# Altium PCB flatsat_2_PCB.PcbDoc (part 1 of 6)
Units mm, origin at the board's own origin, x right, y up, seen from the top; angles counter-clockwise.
Board outline 400 x 250 mm, 4 copper layers (Top Layer, FlatSat GND, FlatSat VCC, Bottom Layer), stack 2.102 mm thick; 196 components, 289 nets, 1724 pads, 1139 vias.
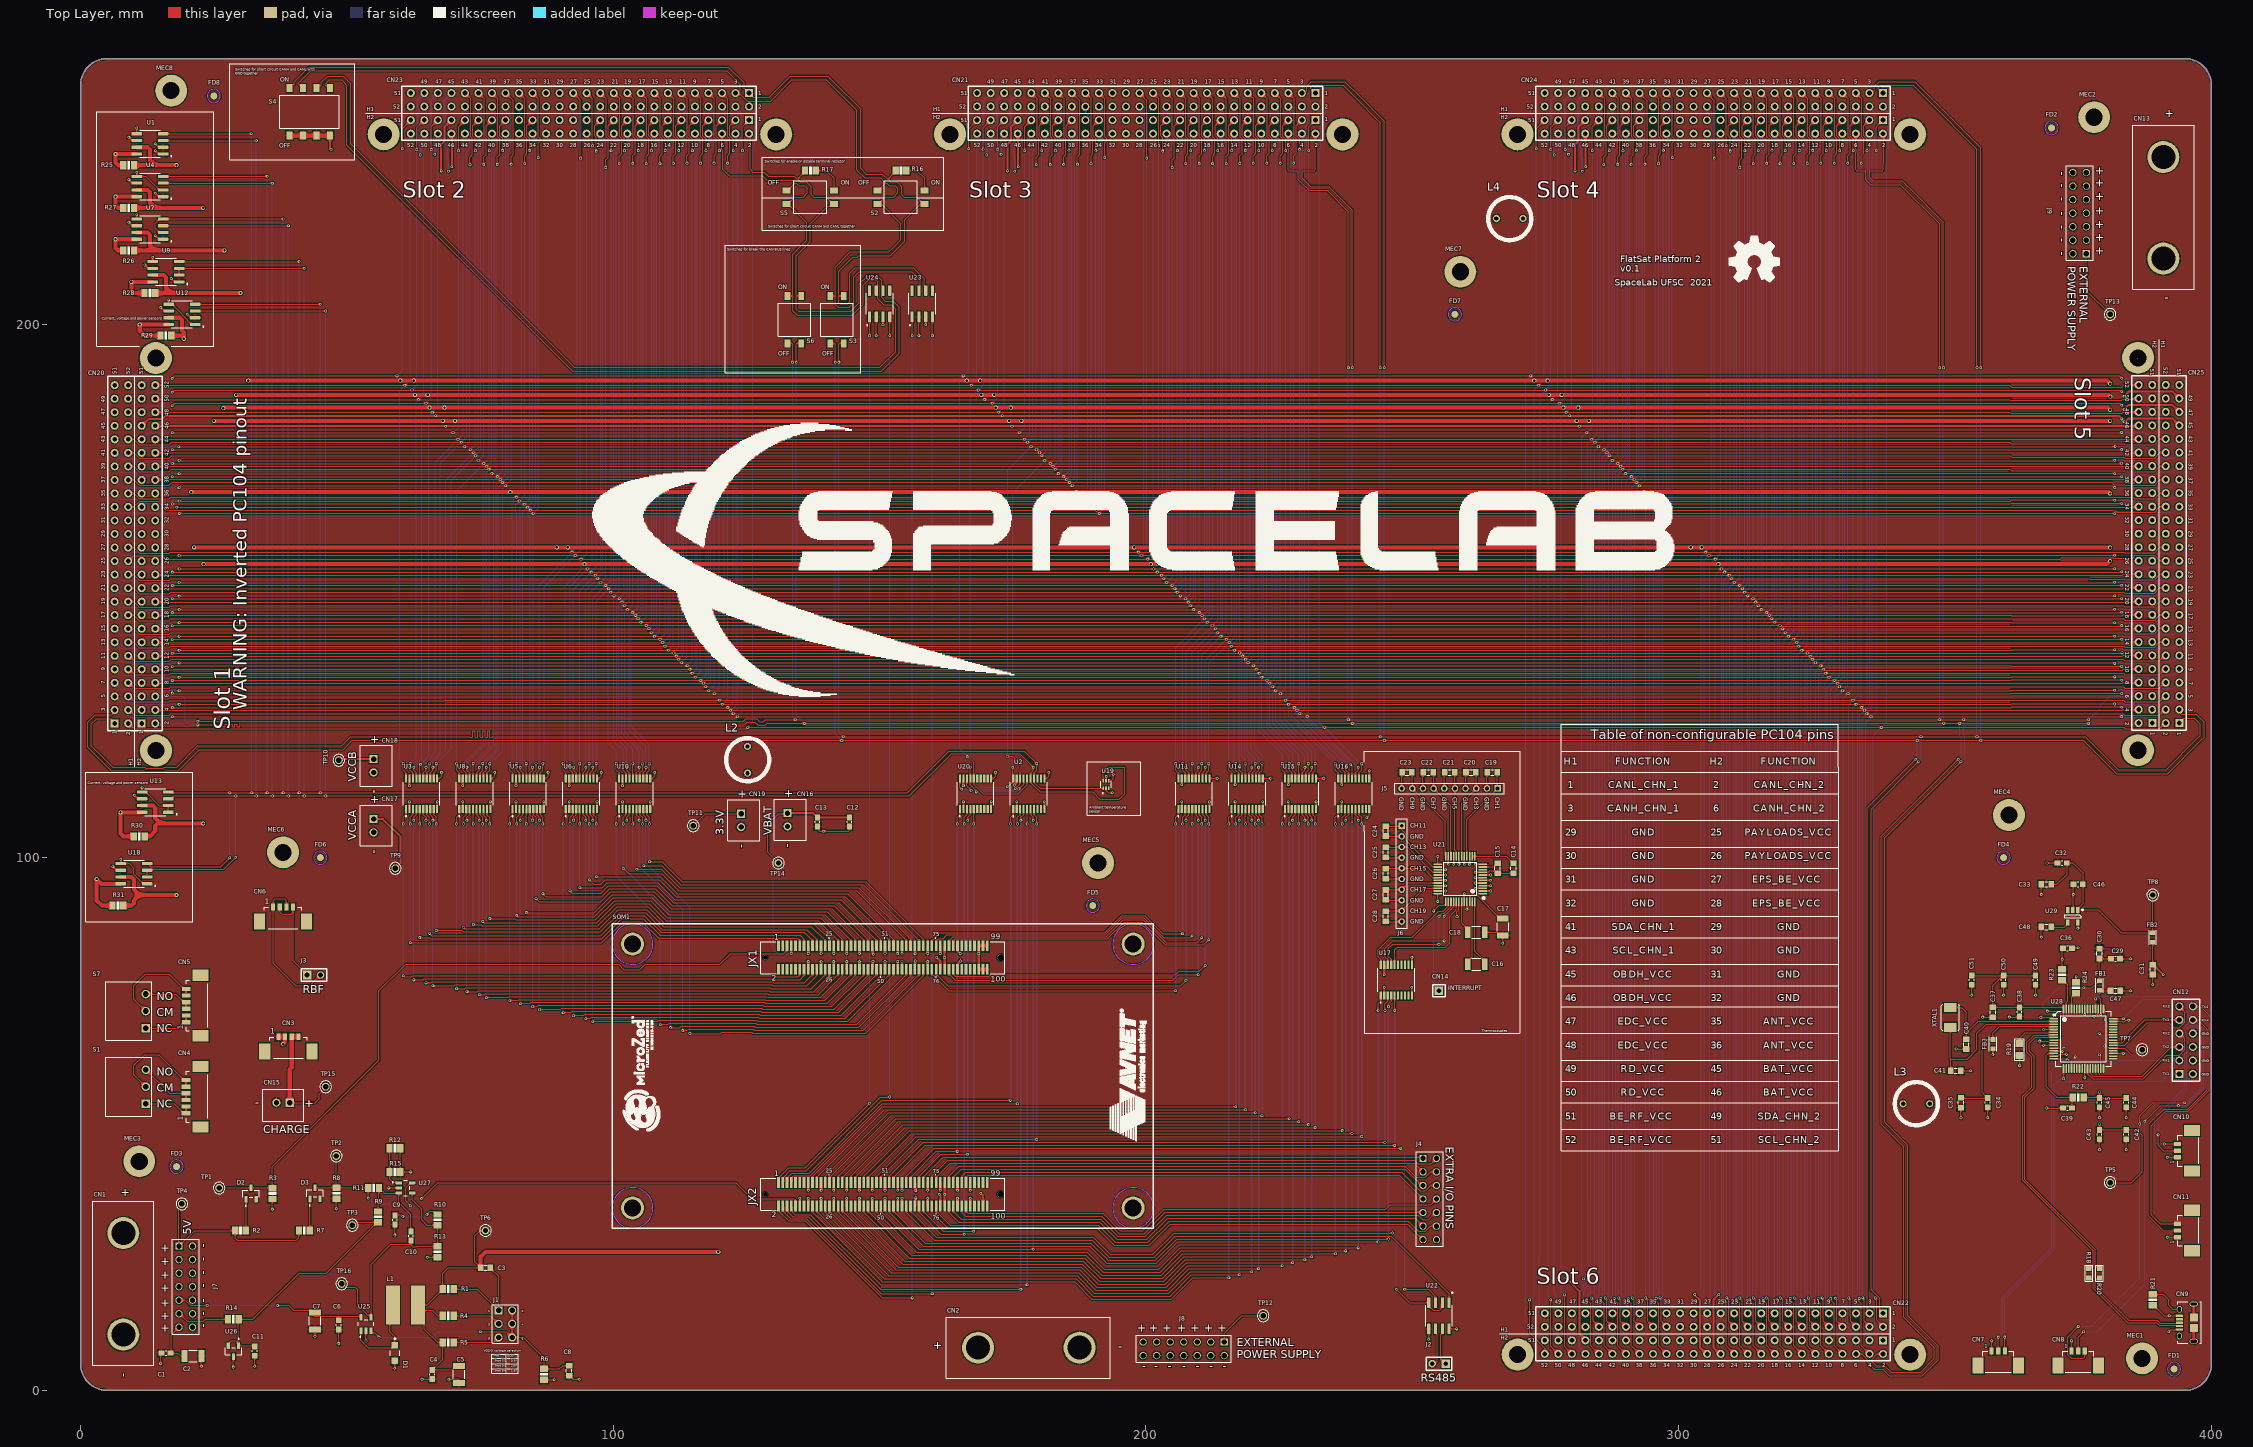
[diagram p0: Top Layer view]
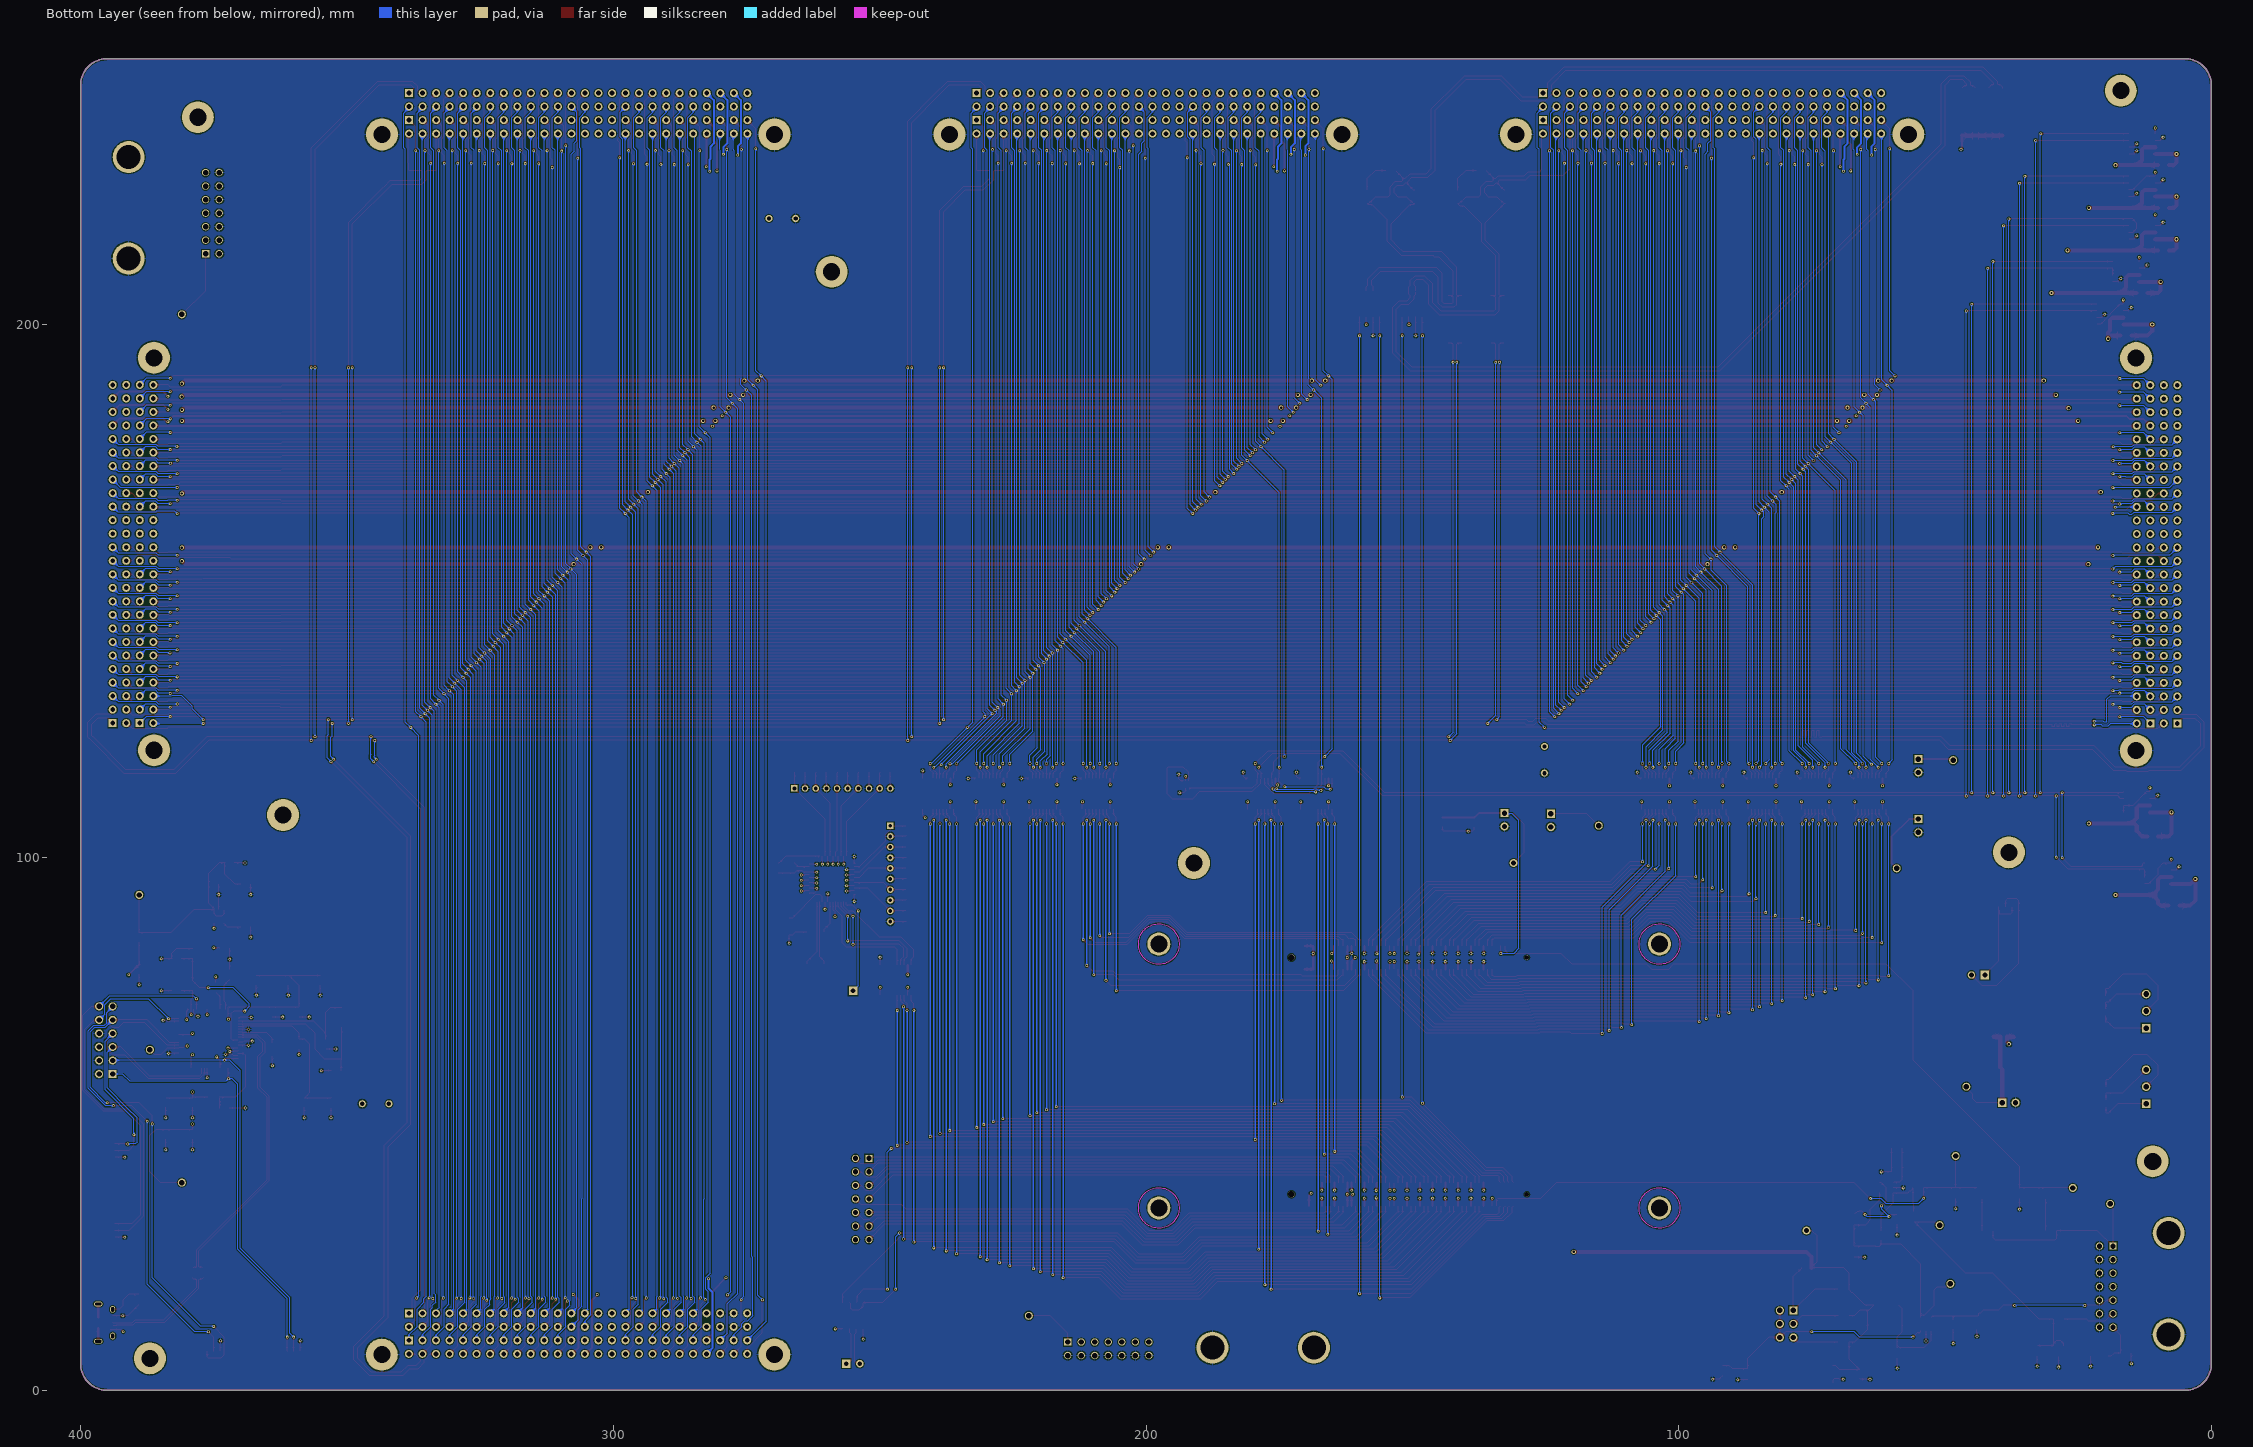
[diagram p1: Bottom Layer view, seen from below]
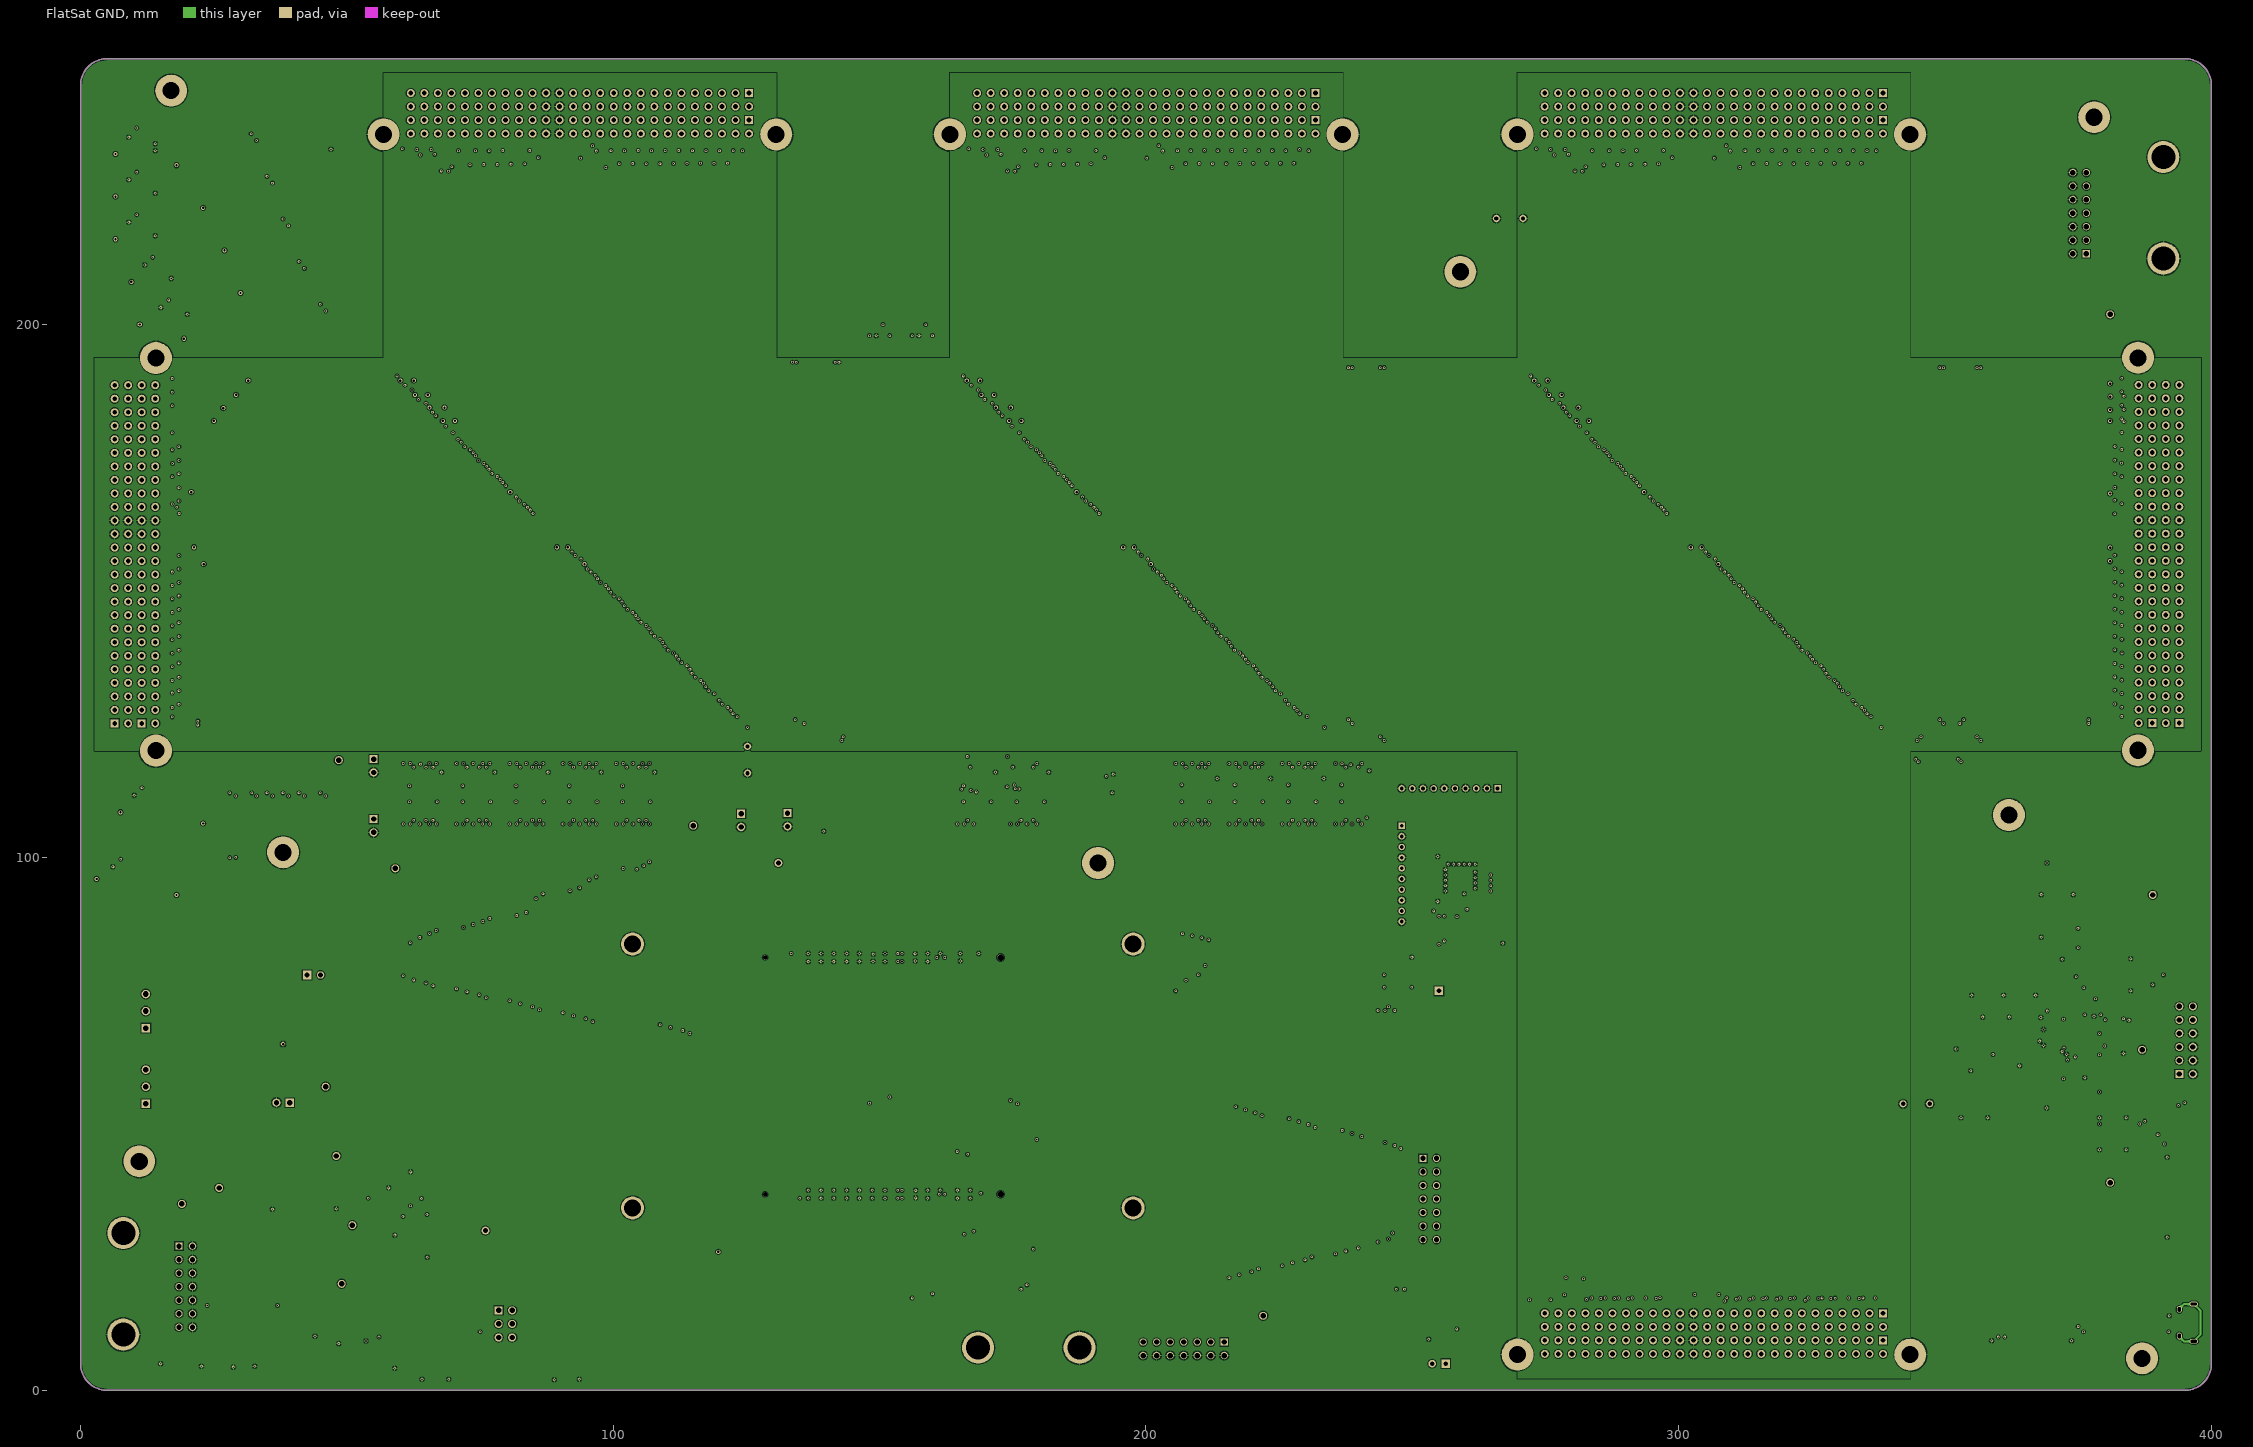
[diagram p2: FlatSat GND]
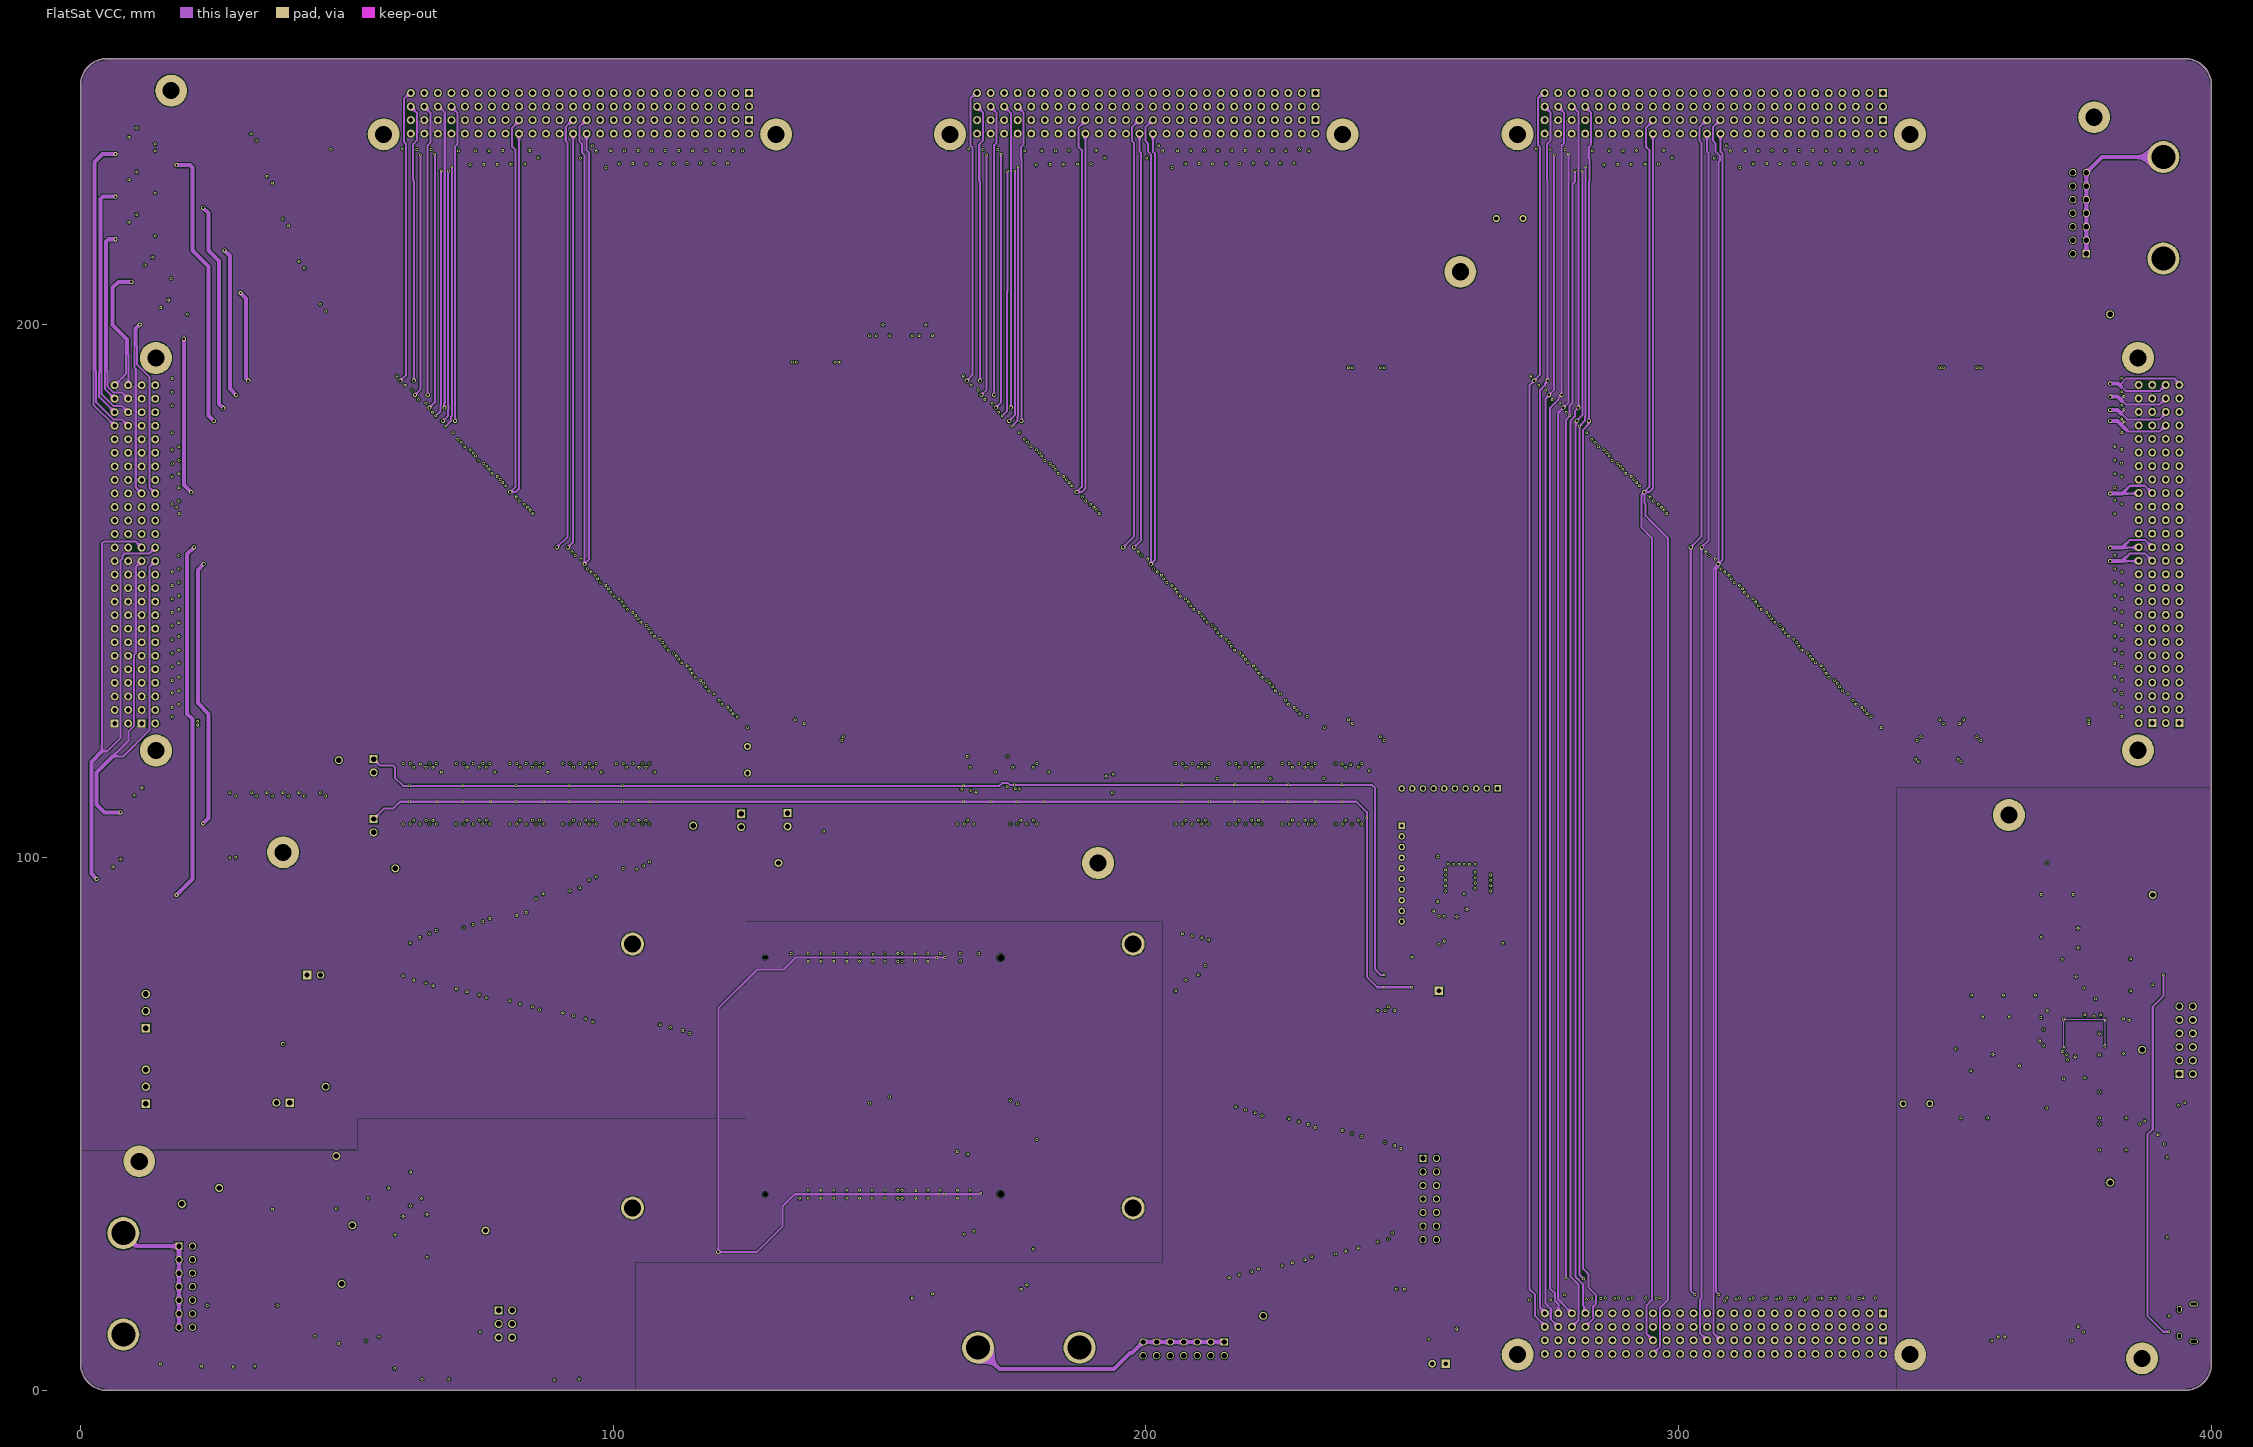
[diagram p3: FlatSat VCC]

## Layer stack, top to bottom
Top Solder: solder mask 0.013, Solder Resist, Dk 3.3
Top Layer: signal copper 0.0356
Dielectric 2: prepreg 0.18, FR-4, Dk 4.29
FlatSat GND: signal copper 0.0356
Dielectric 1: dielectric 1.6, FR-4, Dk 4.29
FlatSat VCC: signal copper 0.0356
Dielectric 3: prepreg 0.18, FR-4, Dk 4.29
Bottom Layer: signal copper 0.0356
Bottom Solder: solder mask 0.013, Solder Resist, Dk 3.3

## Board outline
5,0 cw(c5,5) 0,5 0,245 cw(c5,245) 5,250 395,250 cw(c395,245) 400,245 400,5 cw(c395,5) 395,0

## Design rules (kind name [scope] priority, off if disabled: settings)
Clearance [All] p1: gap=0.178 ignorepadtopadclearanceinfootprint=FALSE
DiffPairsRouting DiffPair_DIFF90DiffPairsRouting [InDifferentialPairClass('DIFF90')] p1: maxlimit=0.254 minlimit=0.203 mostfreqgap=0.233 toplayer_minwidth=0.203 toplayer_maxwidth=0.203 toplayer_prefwidth=0.203 midlayer1_minwidth=0.203 midlayer1_maxwidth=0.203 midlayer1_prefwidth=0.203 midlayer2_minwidth=0.203 midlayer2_maxwidth=0.203 midlayer2_prefwidth=0.203 bottomlayer_minwidth=0.203 bottomlayer_maxwidth=0.203 bottomlayer_prefwidth=0.203 maxuncoupledlength=12.7
DiffPairsRouting DiffPair_DIFF120DiffPairsRouting [InDifferentialPairClass('DIFF120')] p2: maxlimit=5 minlimit=0.381 mostfreqgap=0.508 toplayer_minwidth=0.203 toplayer_maxwidth=0.203 toplayer_prefwidth=0.203 midlayer1_minwidth=0.203 midlayer1_maxwidth=0.203 midlayer1_prefwidth=0.203 midlayer2_minwidth=0.203 midlayer2_maxwidth=0.203 midlayer2_prefwidth=0.203 bottomlayer_minwidth=0.203 bottomlayer_maxwidth=0.203 bottomlayer_prefwidth=0.203 maxuncoupledlength=10
DiffPairsRouting [All] p3: maxlimit=0.254 minlimit=0.254 mostfreqgap=0.254 toplayer_minwidth=0.381 toplayer_maxwidth=0.381 toplayer_prefwidth=0.381 midlayer1_minwidth=0.381 midlayer1_maxwidth=0.381 midlayer1_prefwidth=0.381 midlayer2_minwidth=0.381 midlayer2_maxwidth=0.381 midlayer2_prefwidth=0.381 bottomlayer_minwidth=0.381 bottomlayer_maxwidth=0.381 bottomlayer_prefwidth=0.381 maxuncoupledlength=12.7
HoleSize [All] p1: absolutevalues=TRUE maxlimit=5.08 minlimit=0.025 maxpercent=80.000 minpercent=20.000
MatchedLengths DiffPair_DIFF90MatchedLengths [InDifferentialPairClass('DIFF90')] p1: tolerance=4 checknetsindiffpair=TRUE checkdiffpairvsdiffpair=FALSE checkxsignals=FALSE checkothers=FALSE
MatchedLengths DiffPair_DIFF120MatchedLengths [InDifferentialPairClass('DIFF120')] p2: tolerance=4 checknetsindiffpair=TRUE checkdiffpairvsdiffpair=FALSE checkxsignals=FALSE checkothers=FALSE
MatchedLengths DiffPair_DIFF_120_2MatchedLengths [InDifferentialPairClass('DIFF_120_2')] p3: tolerance=25.4 checknetsindiffpair=FALSE checkdiffpairvsdiffpair=TRUE checkxsignals=TRUE checkothers=TRUE
MatchedLengths DiffPair_DIFF_120_1MatchedLengths [InDifferentialPairClass('DIFF_120_1')] p4: tolerance=25.4 checknetsindiffpair=FALSE checkdiffpairvsdiffpair=TRUE checkxsignals=TRUE checkothers=TRUE
MinimumSolderMaskSliver [All] p1: minsoldermaskwidth=0
PolygonConnect [All] p1: connectstyle=Relief reliefconductorwidth=0.254 reliefentries=4 polygonreliefangle="90 Angle" airgapwidth=0.254
RoutingVias [All] p1: holewidth=0.711 width=1.27 viastyle="Through Hole" minholewidth=0.711 minwidth=1.27 maxholewidth=0.711 maxwidth=1.27
SilkToSilkClearance [All] p1: silktosilkclearance=0.127
SilkToSolderMaskClearance [IsPad] p1: minsilkscreentomaskgap=0 clearancetoexposedcopper=TRUE
SolderMaskExpansion SolderMaskExpansion_Via [IsVia] p1: expansion=0.102
SolderMaskExpansion SolderMaskExpansion_1 [All] p2: expansion=0.102
Width [All] p1: maxlimit=0.762 minlimit=0.203 preferedwidth=0.381 midlayer2_maxwidth=0.381 midlayer2_prefwidth=0.279 bottomlayer_maxwidth=0.381 bottomlayer_prefwidth=0.279 minimp=50.000000 maximp=50.000000 favimp=50.000000
25 further rules are at their usual default settings.

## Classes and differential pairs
component class USB_debug_schematic: C29 C30 C31 C32 C33 C34 C35 C36 C37 C38 C39 C40 C41 C42 C43 C44 C45 C46 C47 C48 C49 C50 C51 CN7 CN8 CN9 CN10 CN11 CN12 FB1 FB2 FB3 R18 R19 R20 R21 R22 R23 R24 U28 U29 XTAL1
component class power_schematic: C1 C2 C3 C4 C5 C6 C7 C8 C9 C10 C11 C12 C13 CN1 CN2 CN3 CN13 CN15 CN16 CN17 CN18 CN19 D1 D2 D3 J1 J7 J8 J9 L1 R1 R2 R3 R4 R5 R6 R7 R8 R9 R10 R11 R12 R13 R14 R15 U25 U26 U27
component class kill-switches_schematic: CN4 CN5 CN6 J3 S1 S7
differential pair USB_TX: +USB_TX_P -USB_TX_N
differential pair USB_RX: +USB_RX_P -USB_RX_N
differential pair RS485: +RS485_P -RS485_N
differential pair H2: +H2_P -H2_N
differential pair H1: +H1_P -H1_N
differential pair CAN_CHN_2: +CAN_CHN_2_P -CAN_CHN_2_N
differential pair CAN_CHN_1: +CAN_CHN_1_P -CAN_CHN_1_N

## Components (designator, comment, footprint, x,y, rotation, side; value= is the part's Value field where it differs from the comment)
C1 "100nF/50V" CC0603 16,7 r180 top
C2 "22uF/16V" CC1210 21.068,6.427 r0 top
C3 "DNP" CC0805 76,23 r0 top
C4 "100nF/50V" CC0603 66,3 r270 top
C5 "22uF/16V" CC1210 71.045,3 r270 top
C6 "100nF/50V" CC0603 48.445,12.3 r270 top
C7 "22uF/16V" CC1210 44,13 r270 top
C8 "DNP" CC0805 91.691,3.7 r90 top
C9 "100nF/50V" CC0603 59,32 r90 top
C10 "100nF/50V" CC0603 62,29 r270 top
C11 "100nF/50V" CC0603 32.67,7.35 r270 top
C12 "100nF/50V" CC0603 144.33,106.7 r270 top
C13 "100nF/50V" CC0603 138.33,106.7 r270 top
C14 "1.0uF/50V" CC0805 269,98 r270 top
C15 "1.0uF/50V" CC0805 266,98 r270 top
C16 "10uF/16V" CC1210 262,80 r180 top
C17 "10uF/16V" CC1210 267,87 r270 top
C18 "10uF/16V" CC1210 262,86 r0 top
C19 "0.1uF/25V" CC0805 265,116 r0 top
C20 "0.1uF/25V" CC0805 261,116 r0 top
C21 "0.1uF/25V" CC0805 257,116 r0 top
C22 "0.1uF/25V" CC0805 253,116 r0 top
C23 "0.1uF/25V" CC0805 249,116 r0 top
C24 "0.1uF/25V" CC0805 245,105 r90 top
C25 "0.1uF/25V" CC0805 245,101 r90 top
C26 "0.1uF/25V" CC0805 245,97 r90 top
C27 "0.1uF/25V" CC0805 245,93 r90 top
C28 "0.1uF/25V" CC0805 245,89 r90 top
C29 "100nF/50V" CC0603 382,81 r0 top
C30 "4.7uF/25V" CC0805 379,82 r90 top
C31 "10nF/50V" CC0805 389,79 r270 top
C32 "100nF/50V" CC0603 372,99 r180 top
C33 "4.7uF/25V" CC0805 369,95 r180 top
C34 "100nF/50V" CC0603 358,54 r270 top
C35 "4.7uF/25V" CC0805 353,54 r270 top
C36 "100nF/50V" CC0603 373,83 r180 top
C37 "4.7uF/25V" CC0805 359,71 r270 top
C38 "100nF/50V" CC0603 364,71 r270 top
C39 "100nF/50V" CC0603 373,53 r180 top
C40 "12pF/50V" CC0805 354,65 r90 top
C41 "12pF/50V" CC0805 352,60 r180 top
C42 "100nF/50V" CC0603 384,48 r270 top
C43 "100nF/50V" CC0603 379,48 r270 top
C44 "100nF/50V" CC0603 384,54 r270 top
C45 "100nF/50V" CC0603 379,54 r270 top
C46 "100nF/50V" CC0603 375,95 r180 top
C47 "4.7uF/25V" CC0805 382,75 r0 top
C48 "10nF/50V" CC0805 369,87 r180 top
C49 "100nF/50V" CC0603 367,77 r270 top
C50 "100nF/50V" CC0603 361,77 r270 top
C51 "100nF/50V" CC0603 355,77 r270 top
CN1 "4243-0" 4243-0 8,20 r90 top
CN2 "4243-0" 4243-0 178,8 r180 top
CN3 "4 pin Picoblade" "PICO BLADE 0533980471" 39,65 r0 top value=0533980471
CN4 "6 pin Picoblade" "PICO BLADE 0533980671" 21.149,55.141 r90 top
CN5 "6 pin Picoblade" "PICO BLADE 0533980671" 21.155,72.241 r90 top
CN6 "4 pin Picoblade" "PICO BLADE 0533980471" 38,89.37 r0 top value=0533980471
CN7 "0533980371" "PICO BLADE 0533980371" 360,6 r0 top
CN8 "0533980371" "PICO BLADE 0533980371" 375,6 r0 top
CN9 "10118194-0001LF" "MICRO USB B 90GRAUS" 395.35,12.7 r90 top
CN10 "0533980371" "PICO BLADE 0533980371" 395,45 r90 top
CN11 "0533980371" "PICO BLADE 0533980371" 395,30 r90 top
CN12 "BCS-106-L-D-TE" BCS-106-L-D-TE 394,59.38 r90 top
CN13 "4243-0" 4243-0 391,222 r90 top
CN14 "TSW-101-05-T-S" "PIN BAR 1 2.54mm 180 GRAUS - Hide" 255,75 r270 top
CN15 "JST 2 position header 2.5mm" B2B-XH-A-M(LF)(SN) 38,54 r180 top
CN16 "JST 2 position header 2.5mm" B2B-XH-A-M(LF)(SN) 132.703,107.107 r270 top
CN17 "JST 2 position header 2.5mm" B2B-XH-A-M(LF)(SN) 55,106 r270 top
CN18 "JST 2 position header 2.5mm" B2B-XH-A-M(LF)(SN) 55,117.25 r270 top
CN19 "JST 2 position header 2.5mm" B2B-XH-A-M(LF)(SN) 124,107 r270 top
CN20 "PC104_inverted" PC104_INVERTED 14.127,125.352 r90 top
CN21 "PC104" PC104 167.894,247.604 r0 top
CN22 "PC104" PC104 274.462,18.527 r0 top
CN23 "PC104" PC104 61.574,247.604 r0 top
CN24 "PC104" PC104 274.434,247.604 r0 top
CN25 "PC104" PC104 398.049,189.161 r270 top
D1 "MBR230LSFT1G" On_Semiconductor_498_MFG 59,7 r270 top
D2 "BAT54LT1G" SOT95P237X112-3N 32,36.945 r90 top
D3 "BAT54LT1G" SOT95P237X112-3N 44,37 r90 top
FB1 "Ferrite Bead 47 Ohms 500mA 100MHz" L0603 379,76 r90 top
FB2 "Ferrite Bead 47 Ohms 500mA 100MHz" L0603 389,85 r90 top
FB3 "Ferrite Bead 47 Ohms 500mA 100MHz" L0603 359,65 r90 top
FD1 "Fiducial 1.3" "FIDUCIAL 1.3MM" 393,4 r0 top
FD2 "Fiducial 1.3" "FIDUCIAL 1.3MM" 370,237 r0 top
FD3 "Fiducial 1.3" "FIDUCIAL 1.3MM" 18,42 r0 top
FD4 "Fiducial 1.3" "FIDUCIAL 1.3MM" 361,100 r0 top
FD5 "Fiducial 1.3" "FIDUCIAL 1.3MM" 190,91 r0 top
FD6 "Fiducial 1.3" "FIDUCIAL 1.3MM" 45,100 r0 top
FD7 "Fiducial 1.3" "FIDUCIAL 1.3MM" 258,202 r0 top
FD8 "Fiducial 1.3" "FIDUCIAL 1.3MM" 25,243 r0 top
J1 "5-146257-3" TE_5-146257-3 79.984,11.952 r0 top
J2 "5-146280-2" "PIN BAR 2 2.54MM 180 GRAUS" 255,5 r180 top
J3 "5-146280-2" "PIN BAR 2 2.54MM 180 GRAUS" 43.771,77.973 r0 top
J4 "87832-1420" SAMTEC_TSW-107-05-F-D 252,43.54 r270 top
J5 "MMS-110-01-L-SV" SAMTEC_MMS-110-01-L-SV 257,113 r180 top
J6 "MMS-110-01-L-SV" SAMTEC_MMS-110-01-L-SV 248,97 r270 top
J7 "87832-1420" SAMTEC_TSW-107-05-F-D 18.46,27.08 r270 top
J8 "87832-1420" SAMTEC_TSW-107-05-F-D 214.699,9.07 r180 top
J9 "87832-1420" SAMTEC_TSW-107-05-F-D 376.54,213.38 r90 top
L1 "3,3 uH" SRR6038 61,16 r0 top
L2 "RL622-3R3K-RC" RL622 125.179,118.392 r90 top
L3 "RL622-3R3K-RC" RL622 344.618,53.782 r180 top
L4 "RL622-3R3K-RC" RL622 268.288,220.012 r0 top
MEC1 "M3" "M3 HOLE" 387,6 r0 top
MEC2 "M3" "M3 HOLE" 378,239 r0 top
MEC3 "M3" "M3 HOLE" 11,43 r0 top
MEC4 "M3" "M3 HOLE" 362,108 r0 top
MEC5 "M3" "M3 HOLE" 191,99 r0 top
MEC6 "M3" "M3 HOLE" 38,101 r0 top
MEC7 "M3" "M3 HOLE" 259,210 r0 top
MEC8 "M3" "M3 HOLE" 17,244 r0 top
R1 "45.3k" 0805 69,19 r180 top
R2 "680R" 0805 30,30 r180 top
R3 "430R" 0805 36,36.945 r90 top
R4 "107k" 0805 69,14 r180 top
R5 "36K" 0805 69,9 r180 top
R6 "10k" 0805 87,3 r90 top
R7 "220R" 0805 42,30 r180 top
R8 "120R" 0805 48,37 r90 top
R9 "3.74k" 0805 55.843,32.562 r270 top
R10 "3k" 0805 67,32 r90 top
R11 "1.0k" 0805 55,38 r180 top
R12 "1.0k" 0805 59,45.44 r0 top
R13 "100k" 0805 67,26 r90 top
R14 "1.0k" 0805 28.67,13.35 r180 top
R15 "1.5k" 0805 59,41 r180 top
R16 "120R" 0805 154,229 r0 top
R17 "120R" 0805 137,229 r0 top
R18 "10R" R0603_MD 377,22 r90 top
R19 "12K" R0805_MD 364,64 r90 top
R20 "10R" R0603_MD 379,22 r90 top
R21 "DNP" 0805 389,17 r90 top
R22 "10k" 0805 375,55 r0 top
R23 "10k" 0805 372,78 r90 top
R24 "10k" 0805 374.619,75.569 r90 top
R25 "DNP" 0805 9,230 r0 top
R26 "DNP" 0805 9,214 r0 top
R27 "DNP" 0805 9,222 r0 top
R28 "DNP" 0805 13,206 r0 top
R29 "DNP" 0805 16,198 r0 top
R30 "DNP" 0805 11,104 r0 top
R31 "DNP" 0805 7,91 r0 top
S1 "1825116-1" SW_1825116-1 12.245,53.8 r90 top
S2 "DS04-254-2-02BK-SMT-TR" SW_DS04-254-2-02BK-SMT-TR 154,224 r0 top
S3 "DS04-254-2-02BK-SMT-TR" SW_DS04-254-2-02BK-SMT-TR 142,201 r90 top
S4 "DS04-254-2-04BK-SMT-TR" SW_DS04-254-2-04BK-SMT-TR 43,240 r90 top
S5 "DS04-254-2-02BK-SMT-TR" SW_DS04-254-2-02BK-SMT-TR 137,224 r0 top
S6 "DS04-254-2-02BK-SMT-TR" SW_DS04-254-2-02BK-SMT-TR 134,201 r90 top
S7 "1825116-1" SW_1825116-1 12.239,68 r90 top
SOM1 "MicroZed" MICROZEDSOM 201.4,30.437 r90 top
TP1 "" "TEST POINT PTH" 26,38 r0 top
TP2 "" "TEST POINT PTH" 48,44 r0 top
TP3 "" "TEST POINT PTH" 51,31 r0 top
TP4 "" "TEST POINT PTH" 19,35 r0 top
TP5 "" "TEST POINT PTH" 381,39 r0 top
TP6 "" "TEST POINT PTH" 76,30 r0 top
TP7 "" "TEST POINT PTH" 387,63.936 r0 top
TP8 "" "TEST POINT PTH" 389,93 r0 top
TP9 "" "TEST POINT PTH" 59.064,98 r0 top
TP10 "" "TEST POINT PTH" 48.459,118.297 r90 top
TP11 "" "TEST POINT PTH" 115,106 r90 top
TP12 "" "TEST POINT PTH" 222,14 r90 top
TP13 "" "TEST POINT PTH" 381,202 r90 top
TP14 "" "TEST POINT PTH" 131,99 r90 top
TP15 "" "TEST POINT PTH" 46,57 r90 top
TP16 "" "TEST POINT PTH" 49,20 r90 top
U1 "INA219AID" SOIC127P599X175-8N 13,234 r180 top
U2 "TXS0108EPWR" SOP65P640X120-20N 178,112 r90 top
U3 "TXB0108PWR" SOP65P640X120-20N 64,112 r90 top
U4 "INA219AID" SOIC127P599X175-8N 13,226 r180 top
U5 "TXB0108PWR" SOP65P640X120-20N 84,112 r90 top
U6 "TXB0108PWR" SOP65P640X120-20N 94,112 r90 top
U7 "INA219AID" SOIC127P599X175-8N 13,218 r180 top
U8 "TXB0108PWR" SOP65P640X120-20N 74,112 r90 top
U9 "INA219AID" SOIC127P599X175-8N 16,210 r180 top
U10 "TXB0108PWR" SOP65P640X120-20N 104,112 r90 top
U11 "TXB0108PWR" SOP65P640X120-20N 209,112 r90 top
U12 "INA219AID" SOIC127P599X175-8N 19,202 r180 top
U13 "INA219AID" SOIC127P599X175-8N 14,110.423 r180 top
U14 "TXB0108PWR" SOP65P640X120-20N 219,112 r90 top
U15 "TXB0108PWR" SOP65P640X120-20N 229,112 r90 top
U16 "TXB0108PWR" SOP65P640X120-20N 239,112 r90 top
U17 "TXB0108PWR" SOP65P640X120-20N 247,77 r90 top
U18 "INA219AID" SOIC127P599X175-8N 10,97 r180 top
U19 "TMP112AIDRLT" SOT50P160X60-6N 192.5,113.735 r90 top
U20 "TXS0108EPWR" SOP65P640X120-20N 168,112 r90 top
U21 "LTC2983CLX#PBF" QFP50P900X900X160-48N 259,96 r180 top
U22 "ISL83483IBZ" SOIC127P600X175-8N 255,14 r270 top
U23 "SN65HVD232D" SOIC127P599X175-8N 158,204 r90 top
U24 "SN65HVD232D" SOIC127P599X175-8N 150,204 r90 top
U25 "LMR10510XMFX/NOPB" SOT95P280X145-5N 53.562,12.44 r90 top
U26 "TL431AIDBZT" SOT95P237X112-3N 28.67,7.35 r270 top
U27 "AP331AWG-7" SOT95P280X145-5N 61,38 r0 top
U28 "FT4232HL-REEL" LQFP-64 376,66 r0 top
U29 "TPS79333DBVR" SOT23-5 374,89 r270 top
XTAL1 "12.000MHz 12pF" "TXC 7A SERIES" 351,70 r270 top

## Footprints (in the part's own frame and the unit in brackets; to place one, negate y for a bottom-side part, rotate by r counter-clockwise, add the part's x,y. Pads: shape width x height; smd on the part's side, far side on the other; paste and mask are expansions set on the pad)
0805 [mil]
  rect 47.24x60 smd: 1(-40,0) 2(40,0)
  silkscreen extent -10,-30 10,30, body extent -50,-24 49,25, height 31
4243-0 [mm]
  round 6 hole 4.5: 0(-9.525,0) 1(9.525,0)
  silkscreen extent -15.28,-5.75 15.48,5.75, body extent -15.12,-5.6 15.28,5.6, height 24.13
B2B-XH-A-M(LF)(SN) [mm]
  rect 1.524x1.524 hole 1: 1(-1.25,0)
  round 1.524 hole 1: 2(1.25,0)
  silkscreen extent -3.88,-2.5 3.8,3.5, body extent -3.75,-2.38 3.65,3.37, height 7.01
BCS-106-L-D-TE [mm]
  rect 1.5x1.5 hole 1: 1(0,0)
  round 1.5 hole 1: 2(2.54,0) 3(5.08,0) 4(7.62,0) 5(10.16,0) 6(12.7,0) 7(0,-2.54) 8(2.54,-2.54) 9(5.08,-2.54) 10(7.62,-2.54) 11(10.16,-2.54) 12(12.7,-2.54)
  silkscreen extent -1.4,-3.87 14.05,1.38, body extent -1.27,-3.81 13.97,1.27, height 7.38
CC0603 [mm]
  rect 1.1x1 smd: 1(-0.85,0) 2(0.85,0)
  silkscreen extent -0.15,-0.45 0.15,0.45, body extent -1,-0.41 1,0.38, height 0.79
CC0805 [mm] "TDK mlccspec_commercial_general_midvoltage_en.pdf"
  rect 1.05x1.2 smd: 1(-0.925,0) 2(0.925,0)
  silkscreen extent -0.3,-0.5 0.3,0.5, body extent -1.25,-0.62 1.25,0.62, height 0.78
CC1210 [mm] "TDK mlccspec_commercial_general_midvoltage_en.pdf"
  rect 1.1x2.2 smd: 1(-1.6,0) 2(1.6,0)
  silkscreen extent -0.8,-1.1 0.8,1.1, body extent -2,-1.24 2,1.24, height 1.69
"FIDUCIAL 1.3MM" [mm]
  round 1.3 smd mask+0.6: FD0(0,0)
  Top Layer keep-out circle w0.1: c0,0 r1.25
L0603 [mm]
  rect 0.9x1 smd: 1(-0.889,0) 2(0.889,0)
  silkscreen extent -1.38,-0.67 1.38,0.67, body extent -0.8,-0.4 0.8,0.4, height 0.95
LQFP-64 [mm] "64-Pin LQFP 0.5 mm Pitch"
  oval 1.65x0.3 smd: 1(-5.575,3.75) 2(-5.575,3.25) 3(-5.575,2.75) 4(-5.575,2.25) 5(-5.575,1.75) 6(-5.575,1.25) 7(-5.575,0.75) 8(-5.575,0.25) 9(-5.575,-0.25) 10(-5.575,-0.75) 11(-5.575,-1.25) 12(-5.575,-1.75) 13(-5.575,-2.25) 14(-5.575,-2.75) 15(-5.575,-3.25) 16(-5.575,-3.75) 33(5.575,-3.75) 34(5.575,-3.25) 35(5.575,-2.75) 36(5.575,-2.25) 37(5.575,-1.75) 38(5.575,-1.25) 39(5.575,-0.75) 40(5.575,-0.25) 41(5.575,0.25) 42(5.575,0.75) 43(5.575,1.25) 44(5.575,1.75) 45(5.575,2.25) 46(5.575,2.75) 47(5.575,3.25) 48(5.575,3.75)
  oval 0.3x1.65 smd: 17(-3.75,-5.575) 18(-3.25,-5.575) 19(-2.75,-5.575) 20(-2.25,-5.575) 21(-1.75,-5.575) 22(-1.25,-5.575) 23(-0.75,-5.575) 24(-0.25,-5.575) 25(0.25,-5.575) 26(0.75,-5.575) 27(1.25,-5.575) 28(1.75,-5.575) 29(2.25,-5.575) 30(2.75,-5.575) 31(3.25,-5.575) 32(3.75,-5.575) 49(3.75,5.575) 50(3.25,5.575) 51(2.75,5.575) 52(2.25,5.575) 53(1.75,5.575) 54(1.25,5.575) 55(0.75,5.575) 56(0.25,5.575) 57(-0.25,5.575) 58(-0.75,5.575) 59(-1.25,5.575) 60(-1.75,5.575) 61(-2.25,5.575) 62(-2.75,5.575) 63(-3.25,5.575) 64(-3.75,5.575)
  silkscreen extent -5.7,-5.2 5.2,5.2, body extent -6,-6 6,6, height 1.6
"M3 HOLE" [mm]
  round 6 hole 3.2: 0(0,0)
"MICRO USB B 90GRAUS" [mm]
  oval 0.9x1.6 hole 0.5 slot 1.2 at 90 deg: 0(-3.5,-1.35) 0(3.5,-1.35)
  oval 1.25x0.95 hole 0.55 slot 0.85 at 0 deg: 0(-2.5,1.35) 0(2.5,1.35)
  rect 1.5x1.5 smd: 0(-1,-1.35) 0(1,-1.35)
  rect 0.4x1.35 smd: 1(-1.3,1.35) 2(-0.65,1.35) 3(0,1.35) 4(0.65,1.35) 5(1.3,1.35)
  silkscreen extent -3.9,-2.78 3.9,1.65, body extent -4.02,-4.03 4.02,1.55, height 2.73
MICROZEDSOM [mil] "MicroZed SOM Footprint"
  round 170 hole 125: 0(150,3850) 0(150,150) 0(2100,3850) 0(2100,150)
  round 30 hole 32.01 unplated: 0(250.5,2870) 0(2000.5,2870)
  round 45.98 hole 47.99 unplated: 0(250.5,1130) 0(2000.5,1130)
  rect 80x20 smd: JX1-1(2087.11,2771.65) JX1-2(1913.89,2771.65) JX1-3(2087.11,2740.16) JX1-4(1913.89,2740.16) JX1-5(2087.11,2708.66) JX1-6(1913.89,2708.66) JX1-7(2087.11,2677.17) JX1-8(1913.89,2677.17) JX1-9(2087.11,2645.67) JX1-10(1913.89,2645.67) JX1-11(2087.11,2614.17) JX1-12(1913.89,2614.17) JX1-13(2087.11,2582.68) JX1-14(1913.89,2582.68) JX1-15(2087.11,2551.18) JX1-16(1913.89,2551.18) JX1-17(2087.11,2519.68) JX1-18(1913.89,2519.69) JX1-19(2087.11,2488.19) JX1-20(1913.89,2488.19) JX1-21(2087.11,2456.69) JX1-22(1913.89,2456.69) JX1-23(2087.11,2425.2) JX1-24(1913.89,2425.2) JX1-25(2087.11,2393.7) JX1-26(1913.89,2393.7) JX1-27(2087.11,2362.2) JX1-28(1913.89,2362.21) JX1-29(2087.11,2330.71) JX1-30(1913.89,2330.71) JX1-31(2087.11,2299.21) JX1-32(1913.89,2299.21) JX1-33(2087.11,2267.72) JX1-34(1913.89,2267.72) JX1-35(2087.11,2236.22) JX1-36(1913.89,2236.22) JX1-37(2087.11,2204.72) JX1-38(1913.89,2204.73) JX1-39(2087.11,2173.23) JX1-40(1913.89,2173.23) JX1-41(2087.11,2141.73) JX1-42(1913.89,2141.73) JX1-43(2087.11,2110.24) JX1-44(1913.89,2110.24) JX1-45(2087.11,2078.74) JX1-46(1913.89,2078.74) JX1-47(2087.11,2047.24) JX1-48(1913.89,2047.25) JX1-49(2087.11,2015.75) JX1-50(1913.89,2015.75) JX1-51(2087.11,1984.25) JX1-52(1913.89,1984.25) JX1-53(2087.11,1952.76) JX1-54(1913.89,1952.76) JX1-55(2087.11,1921.26) JX1-56(1913.89,1921.26) JX1-57(2087.11,1889.76) JX1-58(1913.89,1889.77) JX1-59(2087.11,1858.27) JX1-60(1913.89,1858.27) JX1-61(2087.11,1826.77) JX1-62(1913.89,1826.77) JX1-63(2087.11,1795.28) JX1-64(1913.89,1795.28) JX1-65(2087.11,1763.78) JX1-66(1913.89,1763.78) JX1-67(2087.11,1732.28) JX1-68(1913.89,1732.29) JX1-69(2087.11,1700.79) JX1-70(1913.89,1700.79) JX1-71(2087.11,1669.29) JX1-72(1913.89,1669.29) JX1-73(2087.11,1637.8) JX1-74(1913.89,1637.8) JX1-75(2087.11,1606.3) JX1-76(1913.89,1606.3) JX1-77(2087.11,1574.8) JX1-78(1913.89,1574.81) JX1-79(2087.11,1543.31) JX1-80(1913.89,1543.31) JX1-81(2087.11,1511.81) JX1-82(1913.89,1511.81) JX1-83(2087.11,1480.31) JX1-84(1913.89,1480.32) JX1-85(2087.11,1448.82) JX1-86(1913.89,1448.82) JX1-87(2087.11,1417.32) JX1-88(1913.89,1417.33) JX1-89(2087.11,1385.83) JX1-90(1913.89,1385.83) JX1-91(2087.11,1354.33) JX1-92(1913.89,1354.33) JX1-93(2087.11,1322.83) JX1-94(1913.89,1322.84) JX1-95(2087.11,1291.34) JX1-96(1913.89,1291.34) JX1-97(2087.11,1259.84) JX1-98(1913.89,1259.85) JX1-99(2087.11,1228.35) JX1-100(1913.89,1228.35) JX2-1(337.11,2771.65) JX2-2(163.89,2771.65) JX2-3(337.11,2740.16) JX2-4(163.89,2740.16) JX2-5(337.11,2708.66) JX2-6(163.89,2708.66) JX2-7(337.11,2677.17) JX2-8(163.89,2677.17) JX2-9(337.11,2645.67) JX2-10(163.89,2645.67) JX2-11(337.11,2614.17) JX2-12(163.89,2614.17) JX2-13(337.11,2582.68) JX2-14(163.89,2582.68) JX2-15(337.11,2551.18) JX2-16(163.89,2551.18) JX2-17(337.11,2519.68) JX2-18(163.89,2519.69) JX2-19(337.11,2488.19) JX2-20(163.89,2488.19) JX2-21(337.11,2456.69) JX2-22(163.89,2456.69) JX2-23(337.11,2425.2) JX2-24(163.89,2425.2) JX2-25(337.11,2393.7) JX2-26(163.89,2393.7) JX2-27(337.11,2362.2) JX2-28(163.89,2362.21) JX2-29(337.11,2330.71) JX2-30(163.89,2330.71) JX2-31(337.11,2299.21) JX2-32(163.89,2299.21) JX2-33(337.11,2267.72) JX2-34(163.89,2267.72) JX2-35(337.11,2236.22) JX2-36(163.89,2236.22) JX2-37(337.11,2204.72) JX2-38(163.89,2204.73) JX2-39(337.11,2173.23) JX2-40(163.89,2173.23) JX2-41(337.11,2141.73) JX2-42(163.89,2141.73) JX2-43(337.11,2110.24) JX2-44(163.89,2110.24) JX2-45(337.11,2078.74) JX2-46(163.89,2078.74) JX2-47(337.11,2047.24) JX2-48(163.89,2047.25) JX2-49(337.11,2015.75) JX2-50(163.89,2015.75) JX2-51(337.11,1984.25) JX2-52(163.89,1984.25) JX2-53(337.11,1952.76) JX2-54(163.89,1952.76) JX2-55(337.11,1921.26) JX2-56(163.89,1921.26) JX2-57(337.11,1889.76) JX2-58(163.89,1889.77) JX2-59(337.11,1858.27) JX2-60(163.89,1858.27) JX2-61(337.11,1826.77) JX2-62(163.89,1826.77) JX2-63(337.11,1795.28) JX2-64(163.89,1795.28) JX2-65(337.11,1763.78) JX2-66(163.89,1763.78) JX2-67(337.11,1732.28) JX2-68(163.89,1732.29) JX2-69(337.11,1700.79) JX2-70(163.89,1700.79) JX2-71(337.11,1669.29) JX2-72(163.89,1669.29) JX2-73(337.11,1637.8) JX2-74(163.89,1637.8) JX2-75(337.11,1606.3) JX2-76(163.89,1606.3) JX2-77(337.11,1574.8) JX2-78(163.89,1574.81) JX2-79(337.11,1543.31) JX2-80(163.89,1543.31) JX2-81(337.11,1511.81) JX2-82(163.89,1511.81) JX2-83(337.11,1480.31) JX2-84(163.89,1480.32) JX2-85(337.11,1448.82) JX2-86(163.89,1448.82) JX2-87(337.11,1417.32) JX2-88(163.89,1417.33) JX2-89(337.11,1385.83) JX2-90(163.89,1385.83) JX2-91(337.11,1354.33) JX2-92(163.89,1354.33) JX2-93(337.11,1322.83) JX2-94(163.89,1322.84) JX2-95(337.11,1291.34) JX2-96(163.89,1291.34) JX2-97(337.11,1259.84) JX2-98(163.89,1259.85) JX2-99(337.11,1228.35) JX2-100(163.89,1228.35)
  Top Layer keep-out circle w4: c2100,150 r150
  Top Layer keep-out circle w4: c150,3850 r150
  Top Layer keep-out circle w4: c2100,3850 r150
  Top Layer keep-out circle w4: c150,150 r150
  Bottom Layer keep-out circle w4: c2100,150 r150
  Bottom Layer keep-out circle w4: c150,3850 r150
  Bottom Layer keep-out circle w4: c2100,3850 r150
  Bottom Layer keep-out circle w4: c150,150 r150
  silkscreen extent 0,0 2250,4000, body extent -1,0 2250,4000, height 186
On_Semiconductor_498_MFG [mm]
  rect 1.25x1.22 smd paste+0 mask+0: 1(-1.475,0) 2(1.475,0)
  silkscreen extent -2.8,-0.9 0.48,0.9, body extent -2.2,-1 2.2,1, height 0.25
PC104 [mm] "Connector; Header; 26x4 Position"
  round 6 hole 3.2: 0(-4.686,-11.809) 0(68.998,-11.823)
  rect 1.5x1.5 hole 0.9: 1(63.906,-4.064) 53(63.906,-9.139)
  round 1.5 hole 0.9: 2(63.906,-6.604) 3(61.366,-4.064) 4(61.366,-6.604) 5(58.826,-4.064) 6(58.826,-6.604) 7(56.286,-4.064) 8(56.286,-6.604) 9(53.746,-4.064) 10(53.746,-6.604) 11(51.206,-4.064) 12(51.206,-6.604) 13(48.666,-4.064) 14(48.666,-6.604) 15(46.126,-4.064) 16(46.126,-6.604) 17(43.561,-4.064) 18(43.586,-6.604) 19(41.046,-4.064) 20(41.046,-6.604) 21(38.506,-4.064) 22(38.506,-6.604) 23(35.966,-4.064) 24(35.966,-6.604) 25(33.426,-4.064) 26(33.426,-6.604) 27(30.886,-4.064) 28(30.886,-6.604) 29(28.346,-4.064) 30(28.346,-6.604) 31(25.806,-4.064) 32(25.806,-6.604) 33(23.266,-4.064) 34(23.266,-6.604) 35(20.726,-4.064) 36(20.726,-6.604) 37(18.186,-4.064) 38(18.186,-6.604) 39(15.646,-4.064) 40(15.646,-6.604) 41(13.106,-4.064) 42(13.106,-6.604) 43(10.566,-4.064) 44(10.566,-6.604) 45(8.026,-4.064) 46(8.026,-6.604) 47(5.486,-4.064) 48(5.486,-6.604) 49(2.946,-4.064) 50(2.946,-6.604) 51(0.406,-4.064) 52(0.406,-6.604) 54(63.906,-11.684) 55(61.366,-9.144) 56(61.366,-11.684) 57(58.826,-9.144) 58(58.826,-11.684) 59(56.286,-9.144) 60(56.286,-11.684) 61(53.746,-9.139) 62(53.746,-11.684) 63(51.206,-9.139) 64(51.206,-11.684) 65(48.666,-9.144) 66(48.666,-11.684) 67(46.126,-9.144) 68(46.126,-11.684) 69(43.561,-9.144) 70(43.586,-11.684) 71(41.046,-9.144) 72(41.046,-11.684) 73(38.506,-9.144) 74(38.506,-11.684) 75(35.966,-9.144) 76(35.966,-11.684) 77(33.426,-9.144) 78(33.426,-11.684) 79(30.886,-9.144) 80(30.886,-11.684) 81(28.346,-9.144) 82(28.346,-11.684) 83(25.806,-9.144) 84(25.806,-11.684) 85(23.266,-9.144) 86(23.266,-11.684) 87(20.726,-9.144) 88(20.726,-11.684) 89(18.186,-9.144) 90(18.186,-11.684) 91(15.646,-9.144) 92(15.646,-11.684) 93(13.106,-9.144) 94(13.106,-11.684) 95(10.566,-9.144) 96(10.566,-11.684) 97(8.026,-9.144) 98(8.026,-11.684) 99(5.486,-9.144) 100(5.486,-11.684) 101(2.946,-9.144) 102(2.946,-11.684) 103(0.406,-9.144) 104(0.406,-11.684)
  silkscreen extent -8.03,-12.95 65.28,-2.79, body extent -1.27,-12.83 65.28,-2.92, height 8.52
PC104_INVERTED [mm] "Connector; Header; 26x4 Position"
  round 6 hole 3.2: 0(-5.244,-0.012) 0(68.44,0.002)
  rect 1.5x1.5 hole 0.9: 1(-0.152,7.747) 53(-0.152,2.672)
  round 1.5 hole 0.9: 2(-0.152,5.207) 3(2.388,7.747) 4(2.388,5.207) 5(4.928,7.747) 6(4.928,5.207) 7(7.468,7.747) 8(7.468,5.207) 9(10.008,7.747) 10(10.008,5.207) 11(12.548,7.747) 12(12.548,5.207) 13(15.088,7.747) 14(15.088,5.207) 15(17.628,7.747) 16(17.628,5.207) 17(20.193,7.747) 18(20.168,5.207) 19(22.708,7.747) 20(22.708,5.207) 21(25.248,7.747) 22(25.248,5.207) 23(27.788,7.747) 24(27.788,5.207) 25(30.328,7.747) 26(30.328,5.207) 27(32.868,7.747) 28(32.868,5.207) 29(35.408,7.747) 30(35.408,5.207) 31(37.948,7.747) 32(37.948,5.207) 33(40.488,7.747) 34(40.488,5.207) 35(43.028,7.747) 36(43.028,5.207) 37(45.568,7.747) 38(45.568,5.207) 39(48.108,7.747) 40(48.108,5.207) 41(50.648,7.747) 42(50.648,5.207) 43(53.188,7.747) 44(53.188,5.207) 45(55.728,7.747) 46(55.728,5.207) 47(58.268,7.747) 48(58.268,5.207) 49(60.808,7.747) 50(60.808,5.207) 51(63.348,7.747) 52(63.348,5.207) 54(-0.152,0.127) 55(2.388,2.667) 56(2.388,0.127) 57(4.928,2.667) 58(4.928,0.127) 59(7.468,2.667) 60(7.468,0.127) 61(10.008,2.672) 62(10.008,0.127) 63(12.548,2.672) 64(12.548,0.127) 65(15.088,2.667) 66(15.088,0.127) 67(17.628,2.667) 68(17.628,0.127) 69(20.193,2.667) 70(20.168,0.127) 71(22.708,2.667) 72(22.708,0.127) 73(25.248,2.667) 74(25.248,0.127) 75(27.788,2.667) 76(27.788,0.127) 77(30.328,2.667) 78(30.328,0.127) 79(32.868,2.667) 80(32.868,0.127) 81(35.408,2.667) 82(35.408,0.127) 83(37.948,2.667) 84(37.948,0.127) 85(40.488,2.667) 86(40.488,0.127) 87(43.028,2.667) 88(43.028,0.127) 89(45.568,2.667) 90(45.568,0.127) 91(48.108,2.667) 92(48.108,0.127) 93(50.648,2.667) 94(50.648,0.127) 95(53.188,2.667) 96(53.188,0.127) 97(55.728,2.667) 98(55.728,0.127) 99(58.268,2.667) 100(58.268,0.127) 101(60.808,2.667) 102(60.808,0.127) 103(63.348,2.667) 104(63.348,0.127)
  silkscreen extent -8.29,-1.14 65.02,9.02, body extent -1.27,-1.14 64.77,9.02, height 8.39
"PICO BLADE 0533980371" [mm]
  rect 2.1x3 smd: 0(-3.8,-1.375) 0(3.8,-1.375)
  rect 0.8x1.3 smd: 1(-1.25,1.375) 2(0,1.375) 3(1.25,1.375)
  silkscreen extent -2.9,-2.6 2.9,1.3, body extent -4.45,-2.5 4.45,1.7, height 4.7
"PICO BLADE 0533980471" [mm]
  rect 2.1x3 smd: 0(-4.425,-1.375) 0(4.425,-1.375)
  rect 0.8x1.3 smd: 1(-1.875,1.375) 2(-0.625,1.375) 3(0.625,1.375) 4(1.875,1.375)
  silkscreen extent -3.52,-2.7 3.52,1.3, body extent -5.08,-2.5 5.07,1.7, height 5.88
"PICO BLADE 0533980671" [mm] "CONN HEADER SMD 6POS 1.25MM"
  rect 2.1x3 smd: 0(-5.675,-1.375) 0(5.675,-1.375)
  rect 0.8x1.6 smd: 1(-3.125,1.375) 2(-1.875,1.375) 3(-0.625,1.375) 4(0.625,1.375) 5(1.875,1.375) 6(3.125,1.375)
  silkscreen extent -4.77,-2.7 4.77,1.3, body extent -6.33,-2.5 6.32,1.7, height 5.87
"PIN BAR 1 2.54mm 180 GRAUS - Hide" [mm] "HEADER 1 2.54mm 180 GRAUS"
  rect 1.6x1.6 hole 0.9: 1(0,0)
  silkscreen extent -1.13,-1.2 1.13,1.2, body extent -1.27,-1.24 1.27,1.25, height 8.54
"PIN BAR 2 2.54MM 180 GRAUS" [mm] "HEADER 2 2.54mm 180 GRAUS"
  rect 1.6x1.6 hole 0.9: 1(-1.27,0)
  round 1.398 hole 0.89: 2(1.27,0)
  silkscreen extent -2.4,-1.2 2.4,1.2, body extent -2.54,-1.27 2.54,1.27, height 8.22
QFP50P900X900X160-48N [mm]
  rect 1.6x0.3 smd: 1(-4.25,2.75) 2(-4.25,2.25) 3(-4.25,1.75) 4(-4.25,1.25) 5(-4.25,0.75) 6(-4.25,0.25) 7(-4.25,-0.25) 8(-4.25,-0.75) 9(-4.25,-1.25) 10(-4.25,-1.75) 11(-4.25,-2.25) 12(-4.25,-2.75) 25(4.25,-2.75) 26(4.25,-2.25) 27(4.25,-1.75) 28(4.25,-1.25) 29(4.25,-0.75) 30(4.25,-0.25) 31(4.25,0.25) 32(4.25,0.75) 33(4.25,1.25) 34(4.25,1.75) 35(4.25,2.25) 36(4.25,2.75)
  rect 0.3x1.6 smd: 13(-2.75,-4.25) 14(-2.25,-4.25) 15(-1.75,-4.25) 16(-1.25,-4.25) 17(-0.75,-4.25) 18(-0.25,-4.25) 19(0.25,-4.25) 20(0.75,-4.25) 21(1.25,-4.25) 22(1.75,-4.25) 23(2.25,-4.25) 24(2.75,-4.25) 37(2.75,4.25) 38(2.25,4.25) 39(1.75,4.25) 40(1.25,4.25) 41(0.75,4.25) 42(0.25,4.25) 43(-0.25,4.25) 44(-0.75,4.25) 45(-1.25,4.25) 46(-1.75,4.25) 47(-2.25,4.25) 48(-2.75,4.25)
  silkscreen extent -4.53,-3.1 3.1,3.73, body extent -4.5,-4.5 4.5,4.5, height 1.6
R0603_MD [mm] "Chip Resistor, Body 1.6x0.8mm, IPC Medium Density"
  rect 0.9x1 smd: 1(-0.889,0) 2(0.889,0)
  silkscreen extent -1.5,-0.7 1.5,0.7, body extent -0.8,-0.4 0.8,0.4, height 0.37
R0805_MD [mm] "Chip Resistor, Body 2.0x1.3mm, IPC Medium Density"
  rect 1.3x1.5 smd: 1(-1.143,0) 2(1.143,0)
  silkscreen extent -2,-0.9 2,0.9, body extent -1,-0.62 1,0.63, height 0.47
RL622 [mm]
  round 1.32 hole 0.82: 1(-2.51,-0.02) 2(2.49,-0.01)
  silkscreen extent -4.05,-4.09 4.05,4.01, body extent -4.25,-4.25 4.25,4.25, height 11.01
SAMTEC_MMS-110-01-L-SV [mm]
  rect 1.219x1.219 hole 0.711: 1(-9,0)
  round 1.219 hole 0.711: 2(-7,0) 3(-5,0) 4(-3,0) 5(-1,0) 6(1,0) 7(3,0) 8(5,0) 9(7,0) 10(9,0)
  silkscreen extent -10.28,-1 10.28,1, body extent -10.27,-1 10.27,1, height 4.46
SAMTEC_TSW-107-05-F-D [mm]
  rect 1.37x1.37 hole 1.02: 1(0,0)
  round 1.37 hole 1.02: 2(0,2.54) 3(2.54,0) 4(2.54,2.54) 5(5.08,0) 6(5.08,2.54) 7(7.62,0) 8(7.62,2.54) 9(10.16,0) 10(10.16,2.54) 11(12.7,0) 12(12.7,2.54) 13(15.24,0) 14(15.24,2.54)
  silkscreen extent -1.27,-1.27 16.51,3.81, body extent -1.27,-1.27 16.51,3.81, height 5.22
SOIC127P599X175-8N [mm]
  rrect25% 1.97x0.6 smd: 1(-2.47,1.905) 2(-2.47,0.635) 3(-2.47,-0.635) 4(-2.47,-1.905) 5(2.47,-1.905) 6(2.47,-0.635) 7(2.47,0.635) 8(2.47,1.905)
  silkscreen extent -4.14,-2.52 1.95,2.52, body extent -3,-2.45 3,2.45, height 1.75
SOIC127P600X175-8N [mm]
  rrect25% 1.97x0.6 smd: 1(-2.475,1.905) 2(-2.475,0.635) 3(-2.475,-0.635) 4(-2.475,-1.905) 5(2.475,-1.905) 6(2.475,-0.635) 7(2.475,0.635) 8(2.475,1.905)
  silkscreen extent -4.34,-2.5 2,2.54, body extent -3,-2.45 3,2.45, height 1.75
SOP65P640X120-20N [mm]
  rrect25% 1.57x0.41 smd: 1(-2.87,2.925) 2(-2.87,2.275) 3(-2.87,1.625) 4(-2.87,0.975) 5(-2.87,0.325) 6(-2.87,-0.325) 7(-2.87,-0.975) 8(-2.87,-1.625) 9(-2.87,-2.275) 10(-2.87,-2.925) 11(2.87,-2.925) 12(2.87,-2.275) 13(2.87,-1.625) 14(2.87,-0.975) 15(2.87,-0.325) 16(2.87,0.325) 17(2.87,0.975) 18(2.87,1.625) 19(2.87,2.275) 20(2.87,2.925)
  silkscreen extent -4.29,-3.45 2.2,3.45, body extent -3.2,-3.25 3.2,3.25, height 1.2
SOT23-5 [mm]
  rect 1.1x0.65 smd: 1(-1.2,0.95) 2(-1.2,0) 3(-1.2,-0.95) 4(1.2,-0.95) 5(1.2,0.95)
  silkscreen extent -1.32,-1.55 0.25,1.95, body extent -1.5,-1.5 1.5,1.5, height 1.3
SOT50P160X60-6N [mm]
  rect 0.66x0.31 smd: 1(-0.735,0.5) 2(-0.735,0) 3(-0.735,-0.5) 4(0.735,-0.5) 5(0.735,0) 6(0.735,0.5)
  silkscreen extent -1.7,-0.97 0.6,0.97, body extent -0.8,-0.8 0.8,0.8, height 0.61
SOT95P237X112-3N [mm]
  rrect25% 1.24x0.59 smd: 1(-1.055,0.95) 2(-1.055,-0.95) 3(1.055,0)
  silkscreen extent -2.4,-1.57 0.65,1.57, body extent -1.18,-1.46 1.19,1.46, height 1.12
SOT95P280X145-5N [mm]
  rrect50% 1.21x0.59 smd: 1(-1.255,0.95) 2(-1.255,0) 3(-1.255,-0.95) 4(1.255,-0.95) 5(1.255,0.95)
  silkscreen extent -2.51,-1.45 0.8,1.45, body extent -1.4,-1.45 1.4,1.45, height 1.45
SRR6038 [mil]
  rect 102x287 smd: 1(-92.5,0) 2(92.5,0)
  body extent -138,-138 138,138, height 158
SW_1825116-1 [mm]
  rect 1.605x1.605 hole 1.07: 1(0,0)
  round 1.605 hole 1.07: 2(3.2,0) 3(6.4,0)
  silkscreen extent -2.3,-1.14 8.7,7.5, body extent -2.32,-0.26 8.67,12.24, height 5.61
SW_DS04-254-2-02BK-SMT-TR [mm]
  rect 1.5x1.1 smd: 1A(-4.45,1.27) 1B(4.45,1.27) 2A(-4.45,-1.27) 2B(4.45,-1.27)
  silkscreen extent -3.1,-3.04 3.1,3.04, body extent -4.95,-3.05 4.95,3.03, height 4.01
SW_DS04-254-2-04BK-SMT-TR [mm]
  rect 1.5x1.1 smd: 1A(-4.45,3.81) 1B(4.45,3.81) 2A(-4.45,1.27) 2B(4.45,1.27) 3A(-4.45,-1.27) 3B(4.45,-1.27) 4A(-4.45,-3.81) 4B(4.45,-3.81)
  silkscreen extent -3.1,-5.58 3.1,5.58, body extent -4.95,-5.57 4.95,5.59, height 4.01
TE_5-146257-3 [mm]
  rect 1.53x1.53 hole 1.02: 1(-1.524,3.048)
  round 1.53 hole 1.02: 2(1.016,3.048) 3(-1.524,0.508) 4(1.016,0.508) 5(-1.524,-2.032) 6(1.016,-2.032)
  silkscreen extent -2.79,-8.76 2.19,4.12, body extent -2.69,-3.1 2.18,4.11, height 8.14
"TEST POINT PTH" [mm]
  round 1.5 hole 1: 1(0,0)
  silkscreen extent -1.1,-1.1 1.1,1.1
"TXC 7A SERIES" [mm]
  rect 1.7x2.4 smd: 1(-1.85,0) 2(1.85,0)
  silkscreen extent -2.45,-1.7 2.45,1.7, body extent -2.5,-1.6 2.5,1.6, height 1.35

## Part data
C1 C4 C6 C9 C10 C11 C12 C13 C29 C32 C34 C36 C38 C39 C42 C43 C44 C45 C46 C49 C50 C51: library part Cap_Cer_X7R_100nF_50V_0603, "CAP CER 100nF 50V 10% X7R 0603", Manufacturer Part Number=C0603C104K5RAC3121
C2 C5 C7: library part Cap_Cer_X7R_22uF_16V_1210, "CAP CER 22uF 16V 10% X7R 1210", Manufacturer Part Number=C3225X7R1C226K250AC
C3 C8: library part Cap_DNP_0805, "CAP DNP 0805"
C14 C15: library part Cap_Cer_X7R_1.0uF_50V_0805, "CAP CER 1.0uF 50V 10% X7R 0805", Manufacturer Part Number=C0805X105K5RACAUTO
C16 C17 C18: library part Cap_Cer_X7R_10uF_16V_1210, "CAP CER 10uF 16V 10% X7R 1210", Manufacturer Part Number=C1210C106K4RACTU
C19 C20 C21 C22 C23 C24 C25 C26 C27 C28: library part Cap_Cer_X7R_0.1uF_25V_0805, "CAP CER 0.1uF 25V 10% X7R 0805", Manufacturer Part Number=CC0805KRX7R8BB104
C30 C33 C35 C37 C47: library part Cap_Cer_X7R_4.7uF_25V_0805, "CAP CER 4.7uF 25V 10% X7R 0805", Manufacturer Part Number=C0805C475K3RACAUTO
C31 C48: library part Cap_Cer_X7R_10nF_50V_0805, "CAP CER 0.01uF 50V 10% X7R 0805", Manufacturer Part Number=08055C103KAT4A
C40 C41: library part Cap_Cer_X7R_12pF_50V_0805, "CAP CER 12pF 50V 1% C0G/NP0 0805", Manufacturer Part Number=CL21C120FBANNNC
CN1 CN2 CN13: "POMONA, 4243-0, Binding Post, 4243 Series, 15 A, 60 VDC, Tin Plated Contacts, Brass, Black", Color=Black,Red, Current Rating=15A, Housing Color=Black, Manufacturer="Pomona Electronics", Package Quantity=5, Supplier Part Number 1=501-1126-ND, Voltage Rating=2.5kV, Voltage Rating (AC)=30V, Voltage Rating (DC)=60V
CN3 CN6: library part 0533980471, "1.25mm Pitch PicoBlade™ Header, Surface Mount, Vertical, 4 Circuits", Color=Natural, Contact Resistance=20mR, Current Rating=1A, Flammability Rating="UL94 V-0", Insulation Resistance=100MR, Manufacturer=Molex, Manufacturer Part Number=53398-0471, Max Operating Temperature=85°C, Min Operating Temperature=-40°C, Package Quantity=1000, Supplier Part Number 1=WM7608CT-ND, Voltage Rating=125V
CN4 CN5: library part 53398-0671, "1.25mm Pitch PicoBlade™ Header, Surface Mount, Vertical, 6 Circuits", Color=Natural, Contact Resistance=20mR, Current Rating=1A, Flammability Rating="UL94 V-0", Insulation Resistance=100MR, Manufacturer=Molex, Max Operating Temperature=85°C, Min Operating Temperature=-40°C, Package Quantity=1000, Supplier Part Number 1=WM7610DKR-ND, Voltage Rating=125V
CN7 CN8 CN10 CN11: "CONN HEADER SMD 3POS 1.25MM", Manufacturer=Molex, Manufacturer Part Number=53398-0371
CN9: "CONN USB MICRO B RECPT SMT R/A", Manufacturer=FCI, Supplier Part Number 1=609-4618-1-ND
CN12: "CONN RCPT 12POS 0.1 GOLD PCB", Color=Black, Contact Resistance=10mR, Manufacturer=Samtec, Max Current Rating=5.9A, Max Operating Temperature=125°C, Max Voltage Rating (AC)=475V, Min Operating Temperature=-55°C, Supplier Part Number 1=SAM1008-06-ND
CN14: "CONN HEADER 1POS .100\" SNGL TIN", Manufacturer="Samtec Inc", Supplier Part Number 1=1925384
CN15 CN16 CN17 CN18 CN19: library part B2B-XH-A-M(LF)(SN), "CONN HEADER TOP 2POS 2.5MM GRN", Color=Natural, Manufacturer=JST, Package Quantity=1000, Supplier Part Number 1=455-2879-ND
CN20: Manufacturer Part Number=TSW-126-07-G-D
CN21 CN22 CN23 CN24 CN25: Manufacturer Part Number=SSW-126-01-G-D
FB1 FB2 FB3: library part 742792608, "WURTH ELEKTRONIK   742792608   FERRITE BEAD, 47 OHM, 0.5A, 0603", Case Code (Imperial)=0603, Case Code (Metric)=1608, Case/Package=SMD/SMT, DC Resistance (DCR)=100mR, Inductance=1H, Manufacturer="Wurth Electronics", Max Current Rating=500mA, Max Operating Temperature=125°C, Min Operating Temperature=-55°C, Package Quantity=1, Supplier Part Number 1=732-1596-1-ND, Tolerance=25%
FD1 FD2 FD3 FD4 FD5 FD6 FD7 FD8: "Fiducial 1.3mm"
J1: "Header; Breakaway; 0.100 x 0.100 in.; PC Board; Dual; 6; 0.025 in.; 0.12 in.", Package=None
J2 J3: "02 MODII HDR SRST B/A .100CL", Package=None
J4 J7 J8 J9: "Connector Header Surface Mount 14 position 0.079 _2.00mm_", Manufacturer Part Number=TSW-107-05-F-D, Package=None
J5 J6: "Conn Socket Strip SKT 10 POS 2mm Solder ST Thru-Hole Tube", Package=None
L1: "3.3µH Shielded Wirewound Inductor 3.5A 20mOhm Max Nonstandard", Manufacturer Part Number=SRR6038-3R3Y, Package="Nonstandard Bourns"
L2 L3 L4: "3.3µH Unshielded Wirewound Inductor 5.5A 25mOhm Max Radial, Vertical Cylinder", Package="Radial Bourns - J.W. Miller"
MEC1 MEC2 MEC3 MEC4 MEC5 MEC6 MEC7 MEC8: library part "M3 hole", "M3 hole"
R1: library part R45.3k_1%_1/10W_0805, "RES 45.3K OHM 1/8W 1% 0805", Manufacturer Part Number=RC0805FR-0745K3L
R2: library part R680R_1%_1/8W_0805, "RES 680R OHM 1/8W 1% 0805", Manufacturer Part Number=CRGCQ0805F680R
R3: library part R430R_1%_1/4W_0805, "RES 430R OHM 1/8W 0.1% 0805", Manufacturer Part Number=RT0805BRD07430RL
R4: library part R107k_1%_1/8W_0805, "RES 107K OHM 1/8W 1% 0805", Manufacturer Part Number=RC0805FR-07107KL
R5: library part R36K_1%_1/10W_0805, "RES 36K OHM 1/8W 0.1% 0805", Manufacturer Part Number=RG2012N-363-B-T5
R6 R22 R23 R24: library part R10k_1%_1/8W_0805, "RES 10K OHM 1/8W 1%  0805", Manufacturer Part Number=CRCW080510K0FKEA
R7: library part R220R_1%_1/8W_0805, "RES 220R OHM 1/8W 1% 0805", Manufacturer Part Number=CRCW0805220RFKEA
R8 R16 R17: library part R120R_1%_1/4W_0805, "RES 120R OHM 1/8W 1% 0805", Manufacturer Part Number=CRGCQ0805F120R
R9: library part R3.74k_1%_1/8W_0805, "RES 3.74K OHM 1/8W 0.5% 0805", Manufacturer Part Number=RT0805DRE073K74L
R10: library part R3.0k_1%_1/8W_0805, "RES 3.0K OHM 1/10W 0.1% 0805", Manufacturer Part Number=ERA-6YEB302V
R11 R12 R14: library part R1.0k_1%_1/8W_0805, "RES 1.0K OHM 1/8W 1% 0805", Manufacturer Part Number=RC0805FR-071KL
R13: library part R100k_1%_1/8W_0805, "RES 100K OHM 1/8W 1% 0805", Manufacturer Part Number=AC0805FR-13100KL
R15: library part R1.5K_1%_1/10W_0805, "RES 1.5K OHM 1/10W 0.1% 0805", Manufacturer Part Number=RN73C2A1K5BTDF
R18 R20: library part RC0603FR-0710RL, "RES 10R OHM 1/10W 1% 0603", Case Code (Imperial)=0603, Case Code (Metric)=1608, Manufacturer=Yageo, Max Operating Temperature=155°C, Min Operating Temperature=-55°C, Power Rating=100mW, Supplier Part Number 1=311-10.0HRCT-ND, Temperature Coefficient=200ppm/°C, Tolerance=1%, Voltage Rating=50V
R19: library part RMCF0805FT12K0, "RES 12K OHM 1/8W 1% 0805", Case Code (Imperial)=0805, Case Code (Metric)=2012, Manufacturer="Stackpole Electronics", Max Operating Temperature=155°C, Max Power Dissipation=125mW, Min Operating Temperature=-55°C, Supplier Part Number 1=RMCF0805FT12K0CT-ND, Temperature Coefficient=100ppm/°C, Tolerance=1%
R21: library part RDNP_0805, "RES DNP 0805", Manufacturer Part Number=CRCW08050000Z0EA
R25 R26 R27 R28 R29 R30 R31: library part RDNP_0805, "RES DNP 0805", Manufacturer Part Number=UR73V2ATTD47L0F
S1 S7: "Slide Switch SPDT Through Hole, Right Angle", Package=None
S2 S3 S4 S5 S6: "1 ~ 12 positions, Surface Mount, 2.54 mm Pitch, Slide Actuator, DIP Switch", Package=None
SOM1: library part MicroZed_SOM, "MicroZed SOM Carrier Footprint", Manufacturer Part Number=61083-101400LF
TP1 TP2 TP3 TP4 TP5 TP6 TP7 TP8 TP9 TP10 TP11 TP12 TP13 TP14 TP15 TP16: library part "Test Point PTH", "TEST POINT PAD"
U1 U4 U7 U9 U12 U13 U18: "26V, 12-bit, i2c output current/voltage/power monitor 8-SOIC -40 to 125", Package="SOIC-8 Texas Instruments"
U2 U20: "8-Bit Bidirectional Voltage-Level Shifter For Open-Drain And Push-Pull Application", Package="TSSOP-20 Texas Instruments"
U3 U5 U6 U8 U10 U11 U14 U15 U16 U17: "8-Bit Bidirectional Voltage-Level Shifter with Auto Direction Sensing and +/-15-kV ESD Protect 20-TSSOP -40 to 85", Package="TSSOP-20 Texas Instruments"
U19: "0.5C 1.4V to 3.6V digital temperature sensor with I2C/SMBus in 2.56mm2 package 6-SOT-5X3 -40 to 125", Package="SOT-5X3-6 Texas Instruments"
U21: "IC SENSOR THERMAL", Package="LQFP -48 Analog Devices"
U22: "1/1 Transceiver Half RS422, RS485 8-SOIC", Manufacturer Part Number=ISL83483IBZ-T, Package="SOIC-8 Intersil"
U23 U24: "3.3 V CAN Transceiver", Package="SOIC-8 Texas Instruments"
U25: Package=None
U26: "Shunt Voltage Reference IC 36V ±1% SOT-23-3", Package="SOT-23-3 Texas Instruments"
U28: "FTDI - FT4232HL-REEL - USB-UART/MPSSE, 4232, QUAD, 64LQFP", Case/Package=LQFP, Dual Supply Voltage=3.3V, Manufacturer=FTDI, Max Operating Temperature=85°C, Max Supply Voltage=3.63V, Min Operating Temperature=-40°C, Min Supply Voltage=1.62V, Operating Supply Current=70mA, Package Quantity=1000, Supplier Part Number 1=768-1026-1-ND
U29: "TEXAS INSTRUMENTS - TPS79333DBVR - IC, V REG, LINEAR, 0.2A, SOT-23-5", Case/Package=SOT-23, Current Rating=200mA, Dropout Voltage=102mV, Input Bias Current=170uA, Manufacturer="Texas Instruments", Max Input Voltage=5.5V, Max Operating Temperature=125°C, Max Output Voltage=3.3V, Max Power Dissipation=560mW, Min Current Limit=285mA, Min Input Voltage=2.7V, Min Operating Temperature=-40°C, Output Voltage Accuracy=2%, Package Quantity=1, Quiescent Current=200uA, Supplier Part Number 1=296-12961-1-ND
XTAL1: library part AA-12.000MAGE-T, "Crystals 12.000MHz 30ppm 12pF -40C to 85C", Case/Package=SMD/SMT, ESR (Equivalent Series Resistance)=100R, Frequency=12MHz, Frequency Stability=50ppm, Frequency Tolerance=30ppm, Manufacturer=TXC, Max Operating Temperature=85°C, Min Operating Temperature=-40°C, Package Quantity=1000, Ratings=AEC-Q200, Supplier Part Number 1=887-1656-1-ND

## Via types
v1: diameter 0.508, hole 0.3, Top Layer to Bottom Layer, tented both sides, 1073 vias
v2: diameter 0.762, hole 0.45, Top Layer to Bottom Layer, tented both sides, 66 vias

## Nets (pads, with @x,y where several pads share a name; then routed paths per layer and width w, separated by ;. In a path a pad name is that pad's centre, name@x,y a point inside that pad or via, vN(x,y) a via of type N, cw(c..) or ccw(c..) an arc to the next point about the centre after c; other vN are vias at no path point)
2.5V: C11.1 R9.2 R14.1 TP3.1 U26.1 U26.2 | length 49.4
  Top Layer w0.203: U26.2@27.72,8.405 27.72,8.73 28.265,9.275 29.075,9.275 U26.1@29.62,8.73 ; C11.1@32.67,8.275 32.54,8.405 U26.1@29.62,8.405 U26.1@29.62,8.73 ; TP3.1@51,31 51.351,31 51.897,31.546 R9.2@55.681,31.546 ; R9.2@55.843,31.546 R9.2@55.681,31.546 ; U26.1@29.62,8.73 29.62,13.284 R14.1@29.686,13.35 32.35,13.35 33,14 41,22 46.135,22 R9.2@55.681,31.546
